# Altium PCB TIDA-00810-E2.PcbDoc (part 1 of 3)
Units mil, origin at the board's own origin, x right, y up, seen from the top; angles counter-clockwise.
Board outline 4527.56 x 3740.16 mil, 4 copper layers (Top Layer, Signal Layer 1, Signal Layer 2, Bottom Layer), stack 25.634 mil thick; 448 components, 198 nets, 1031 pads, 344 vias.
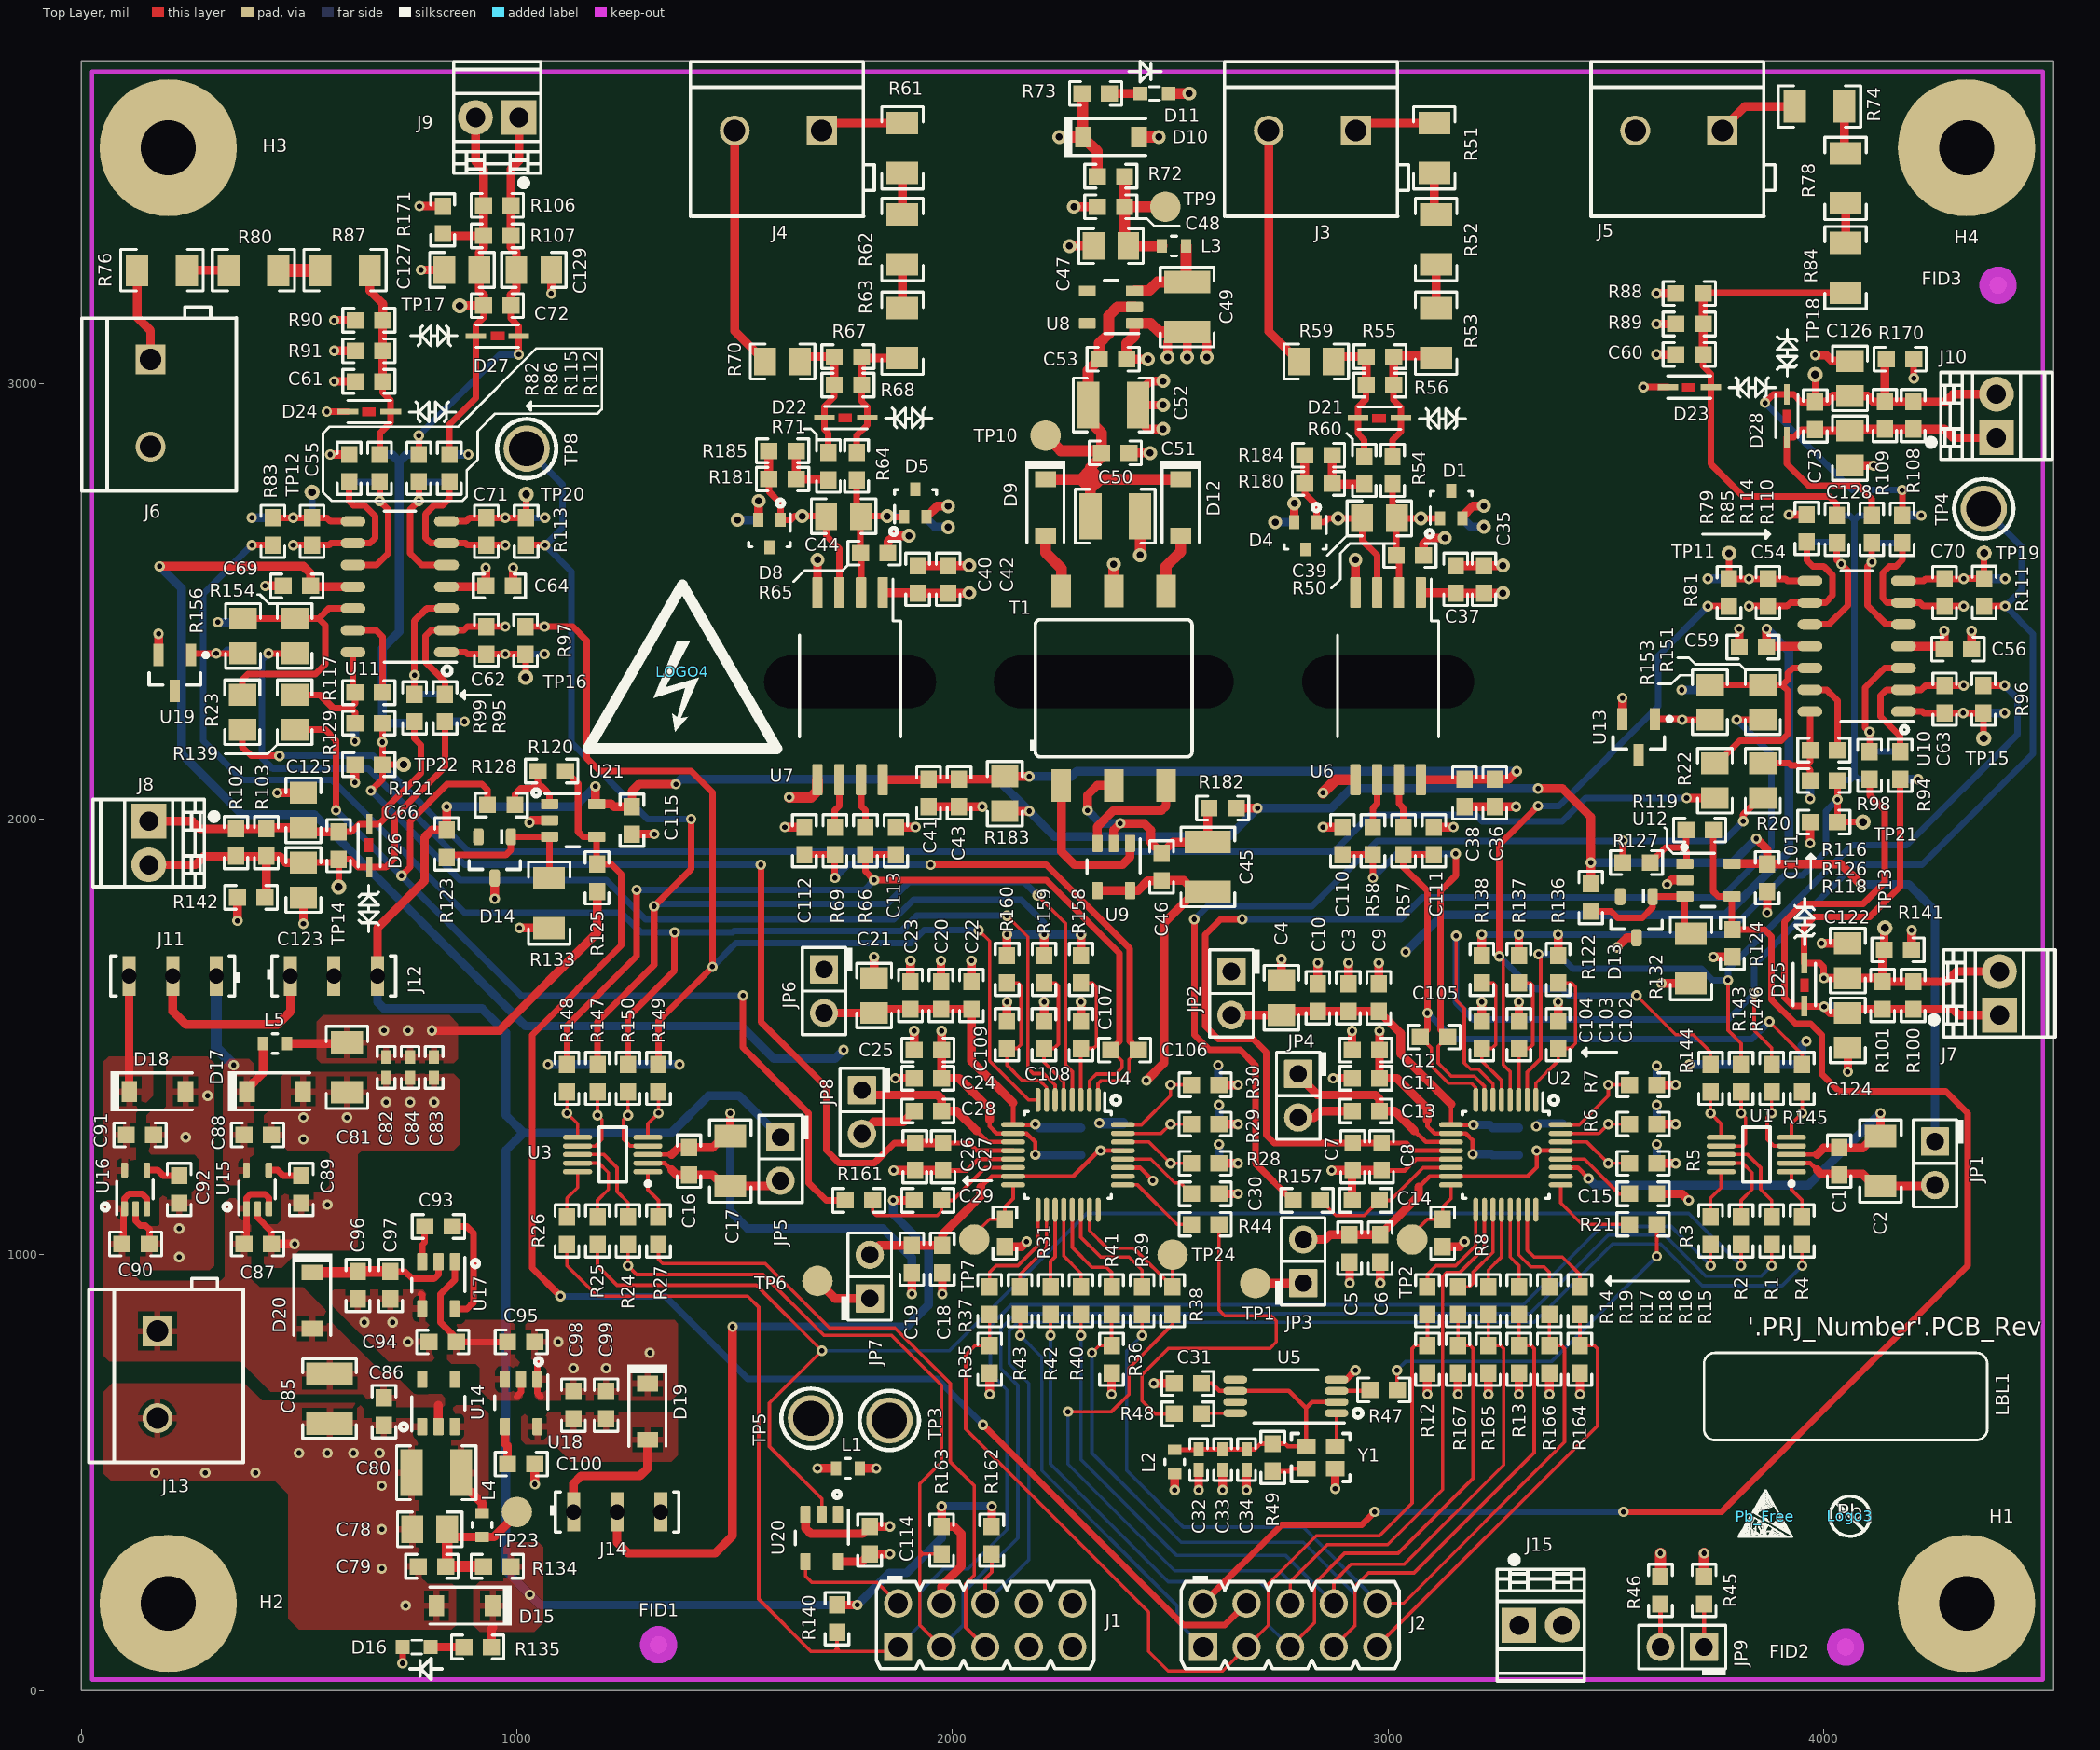
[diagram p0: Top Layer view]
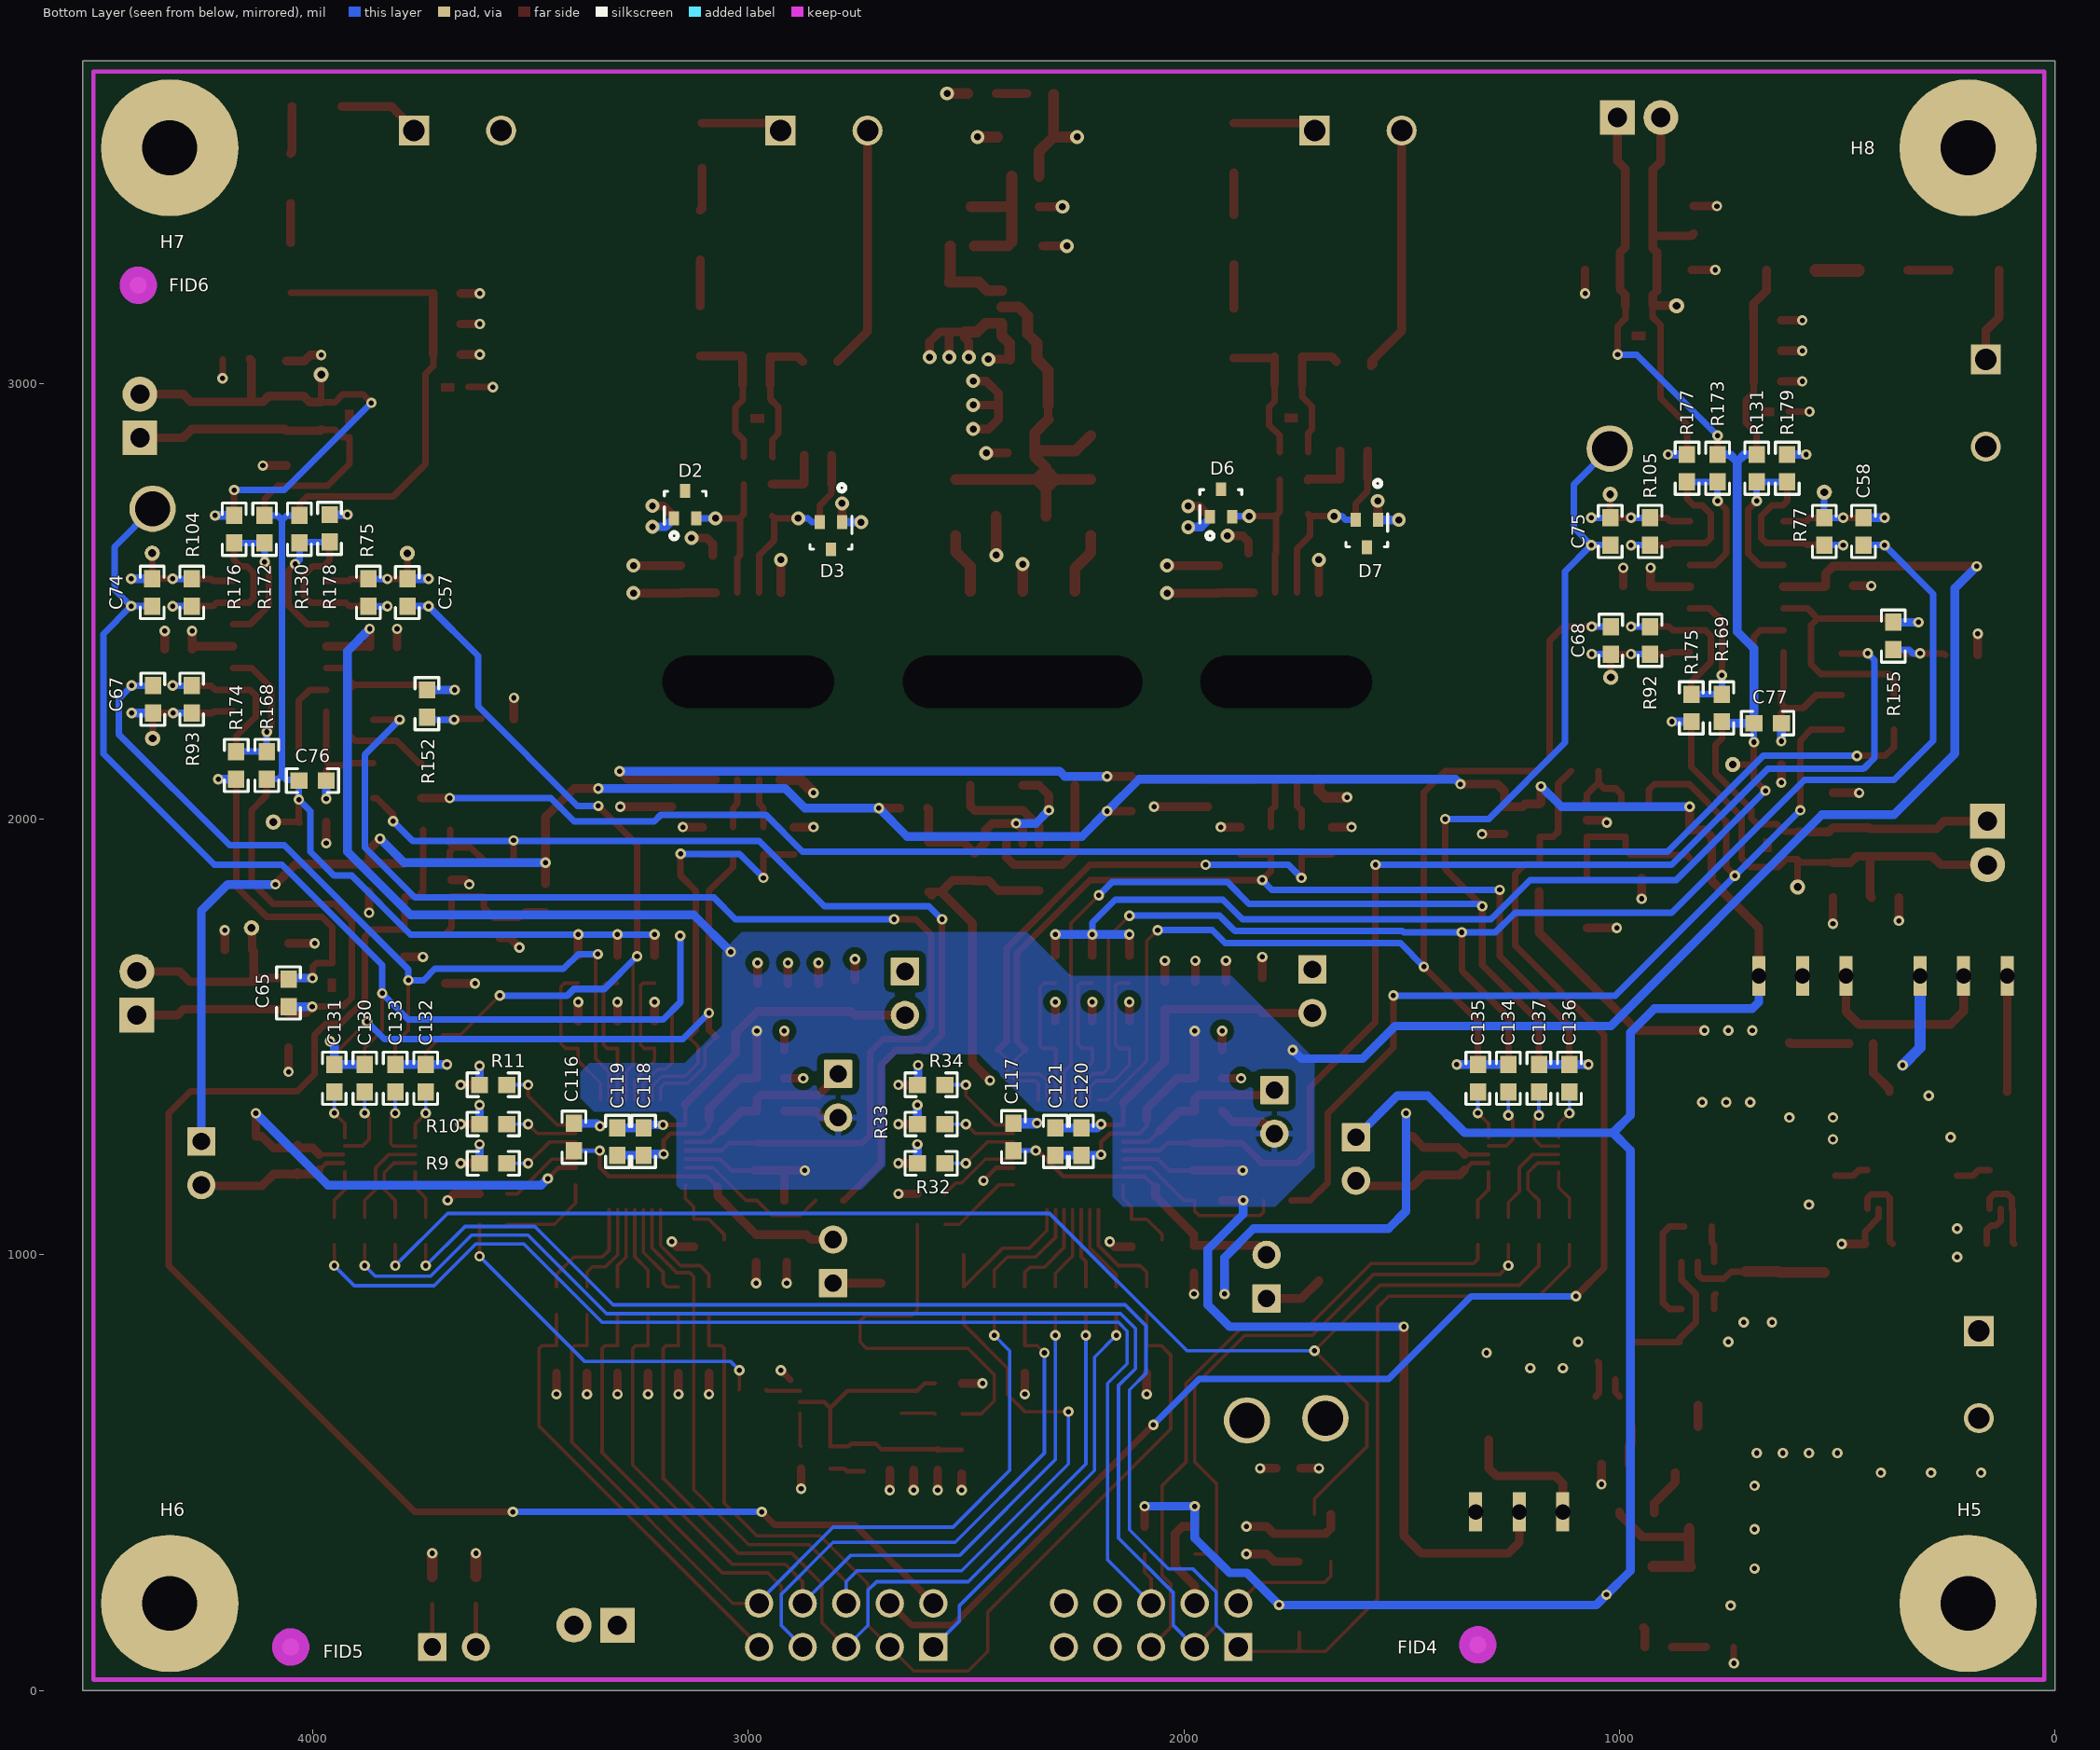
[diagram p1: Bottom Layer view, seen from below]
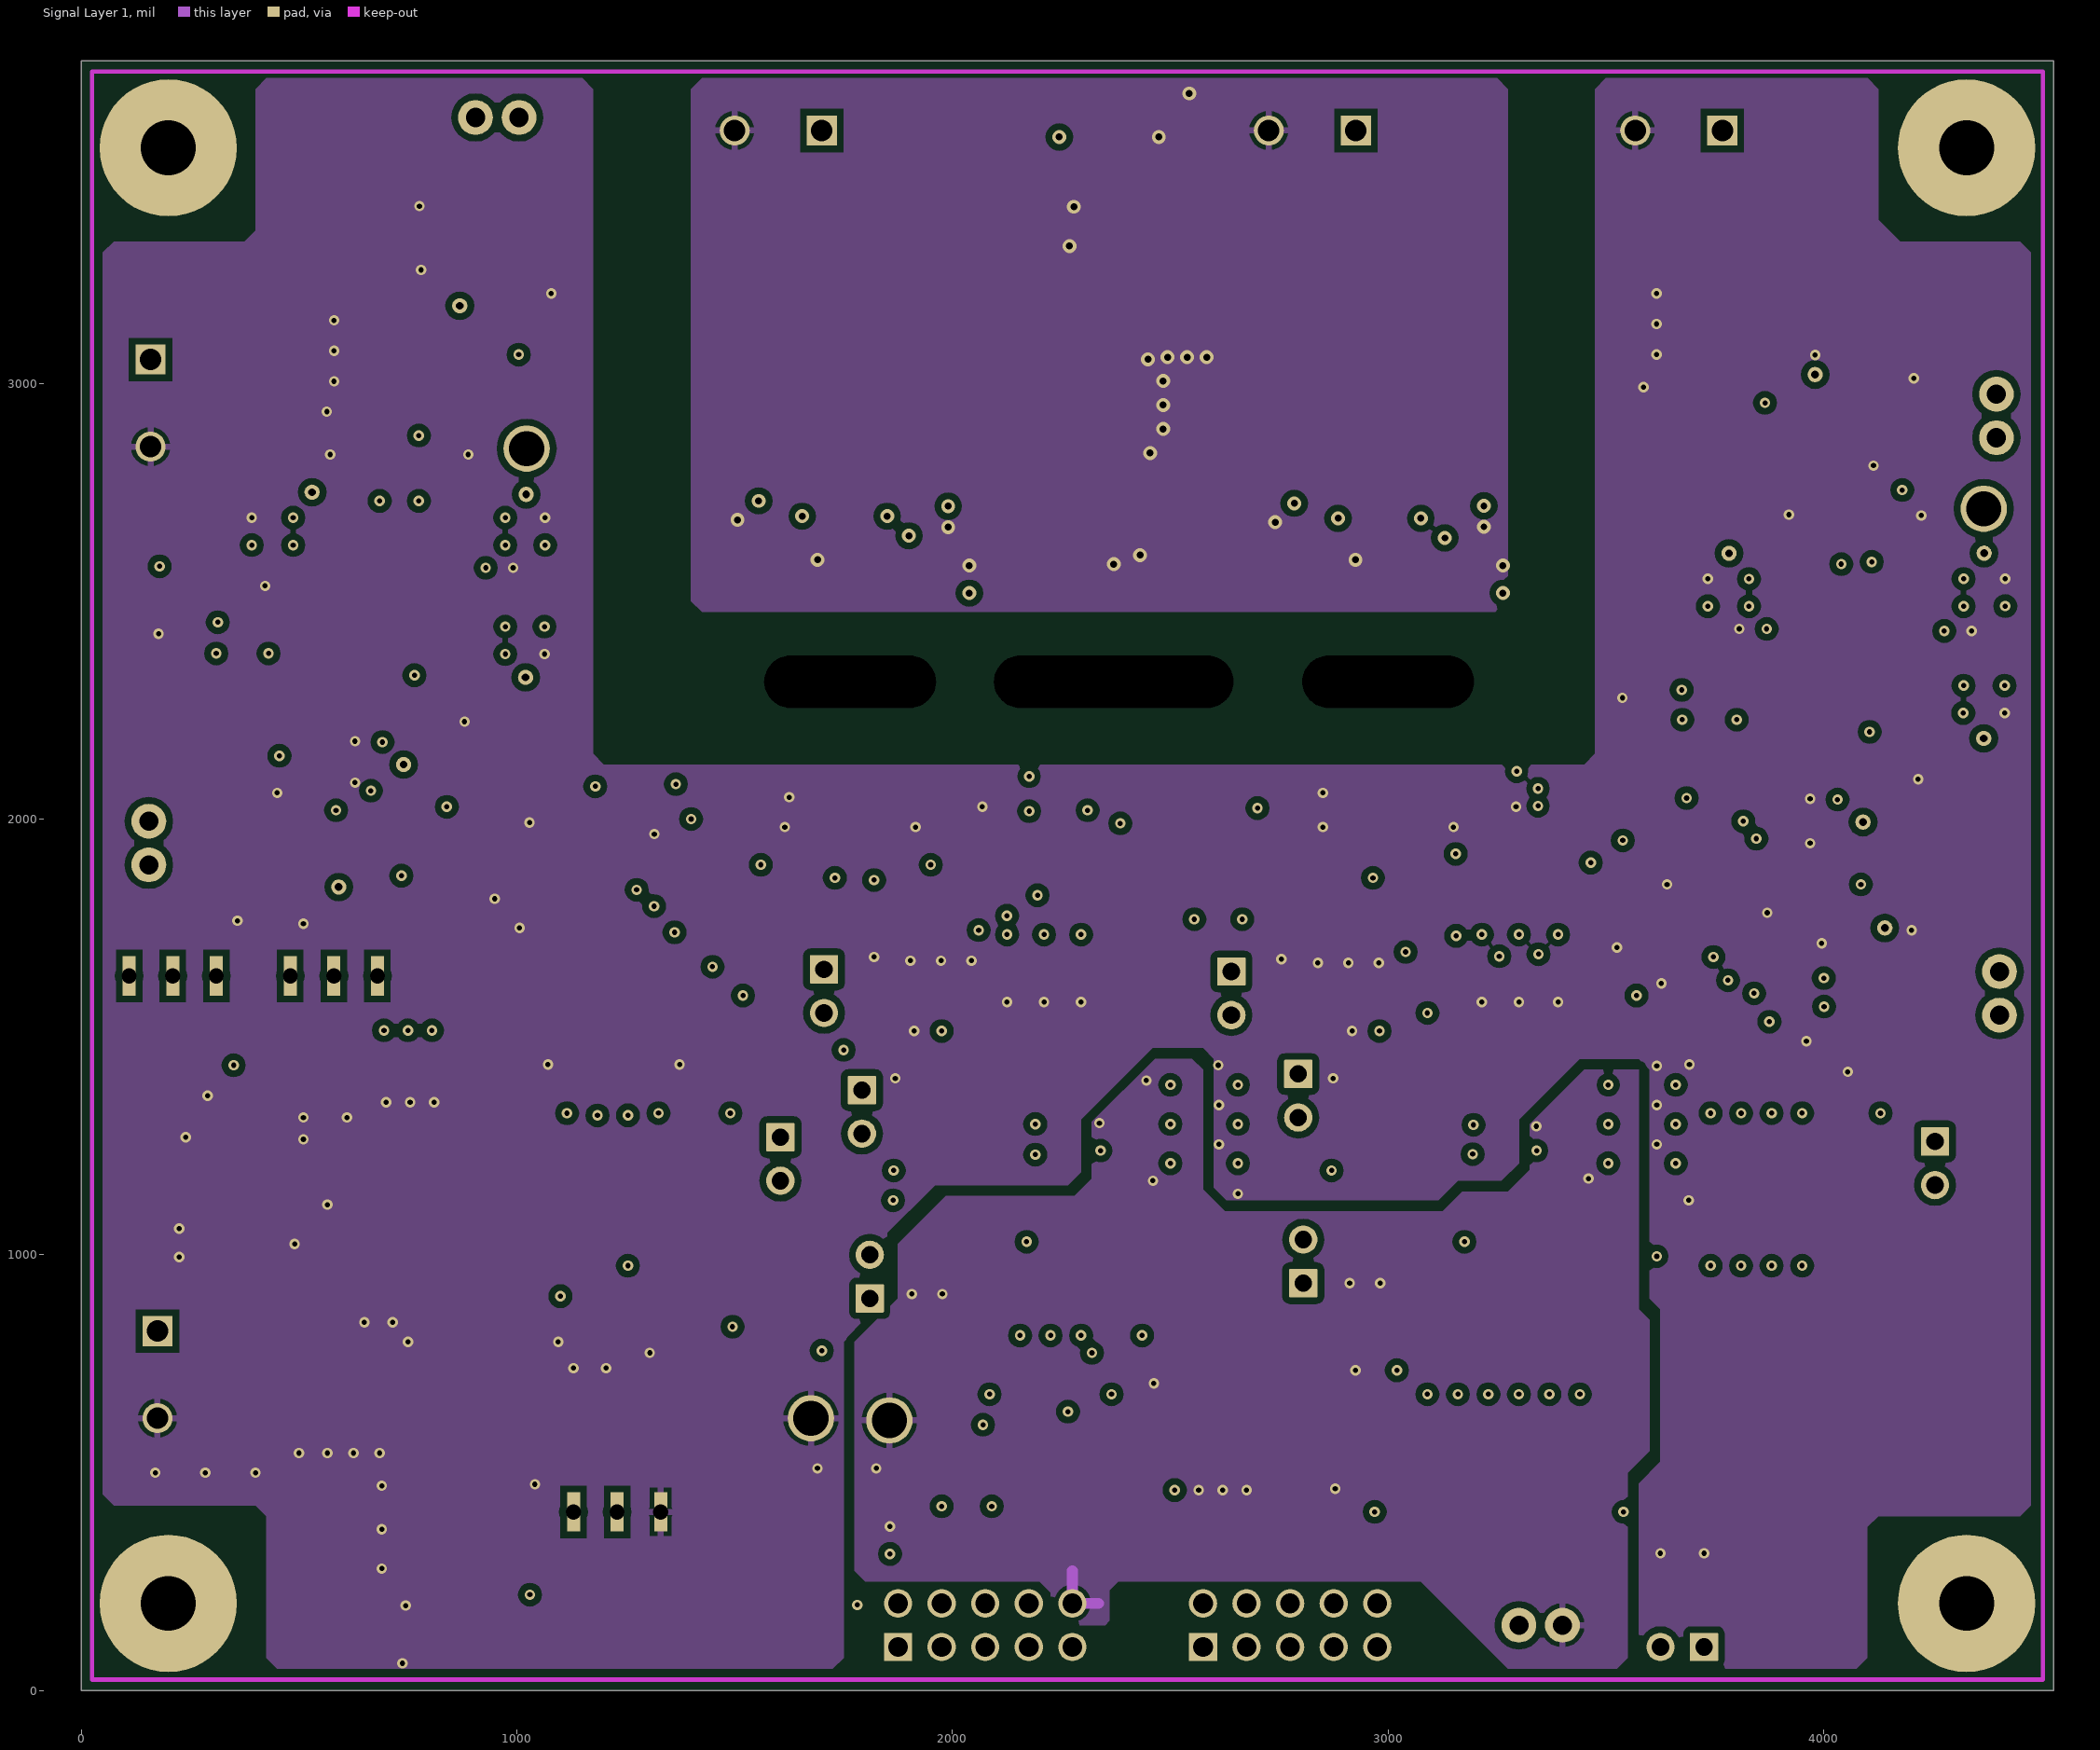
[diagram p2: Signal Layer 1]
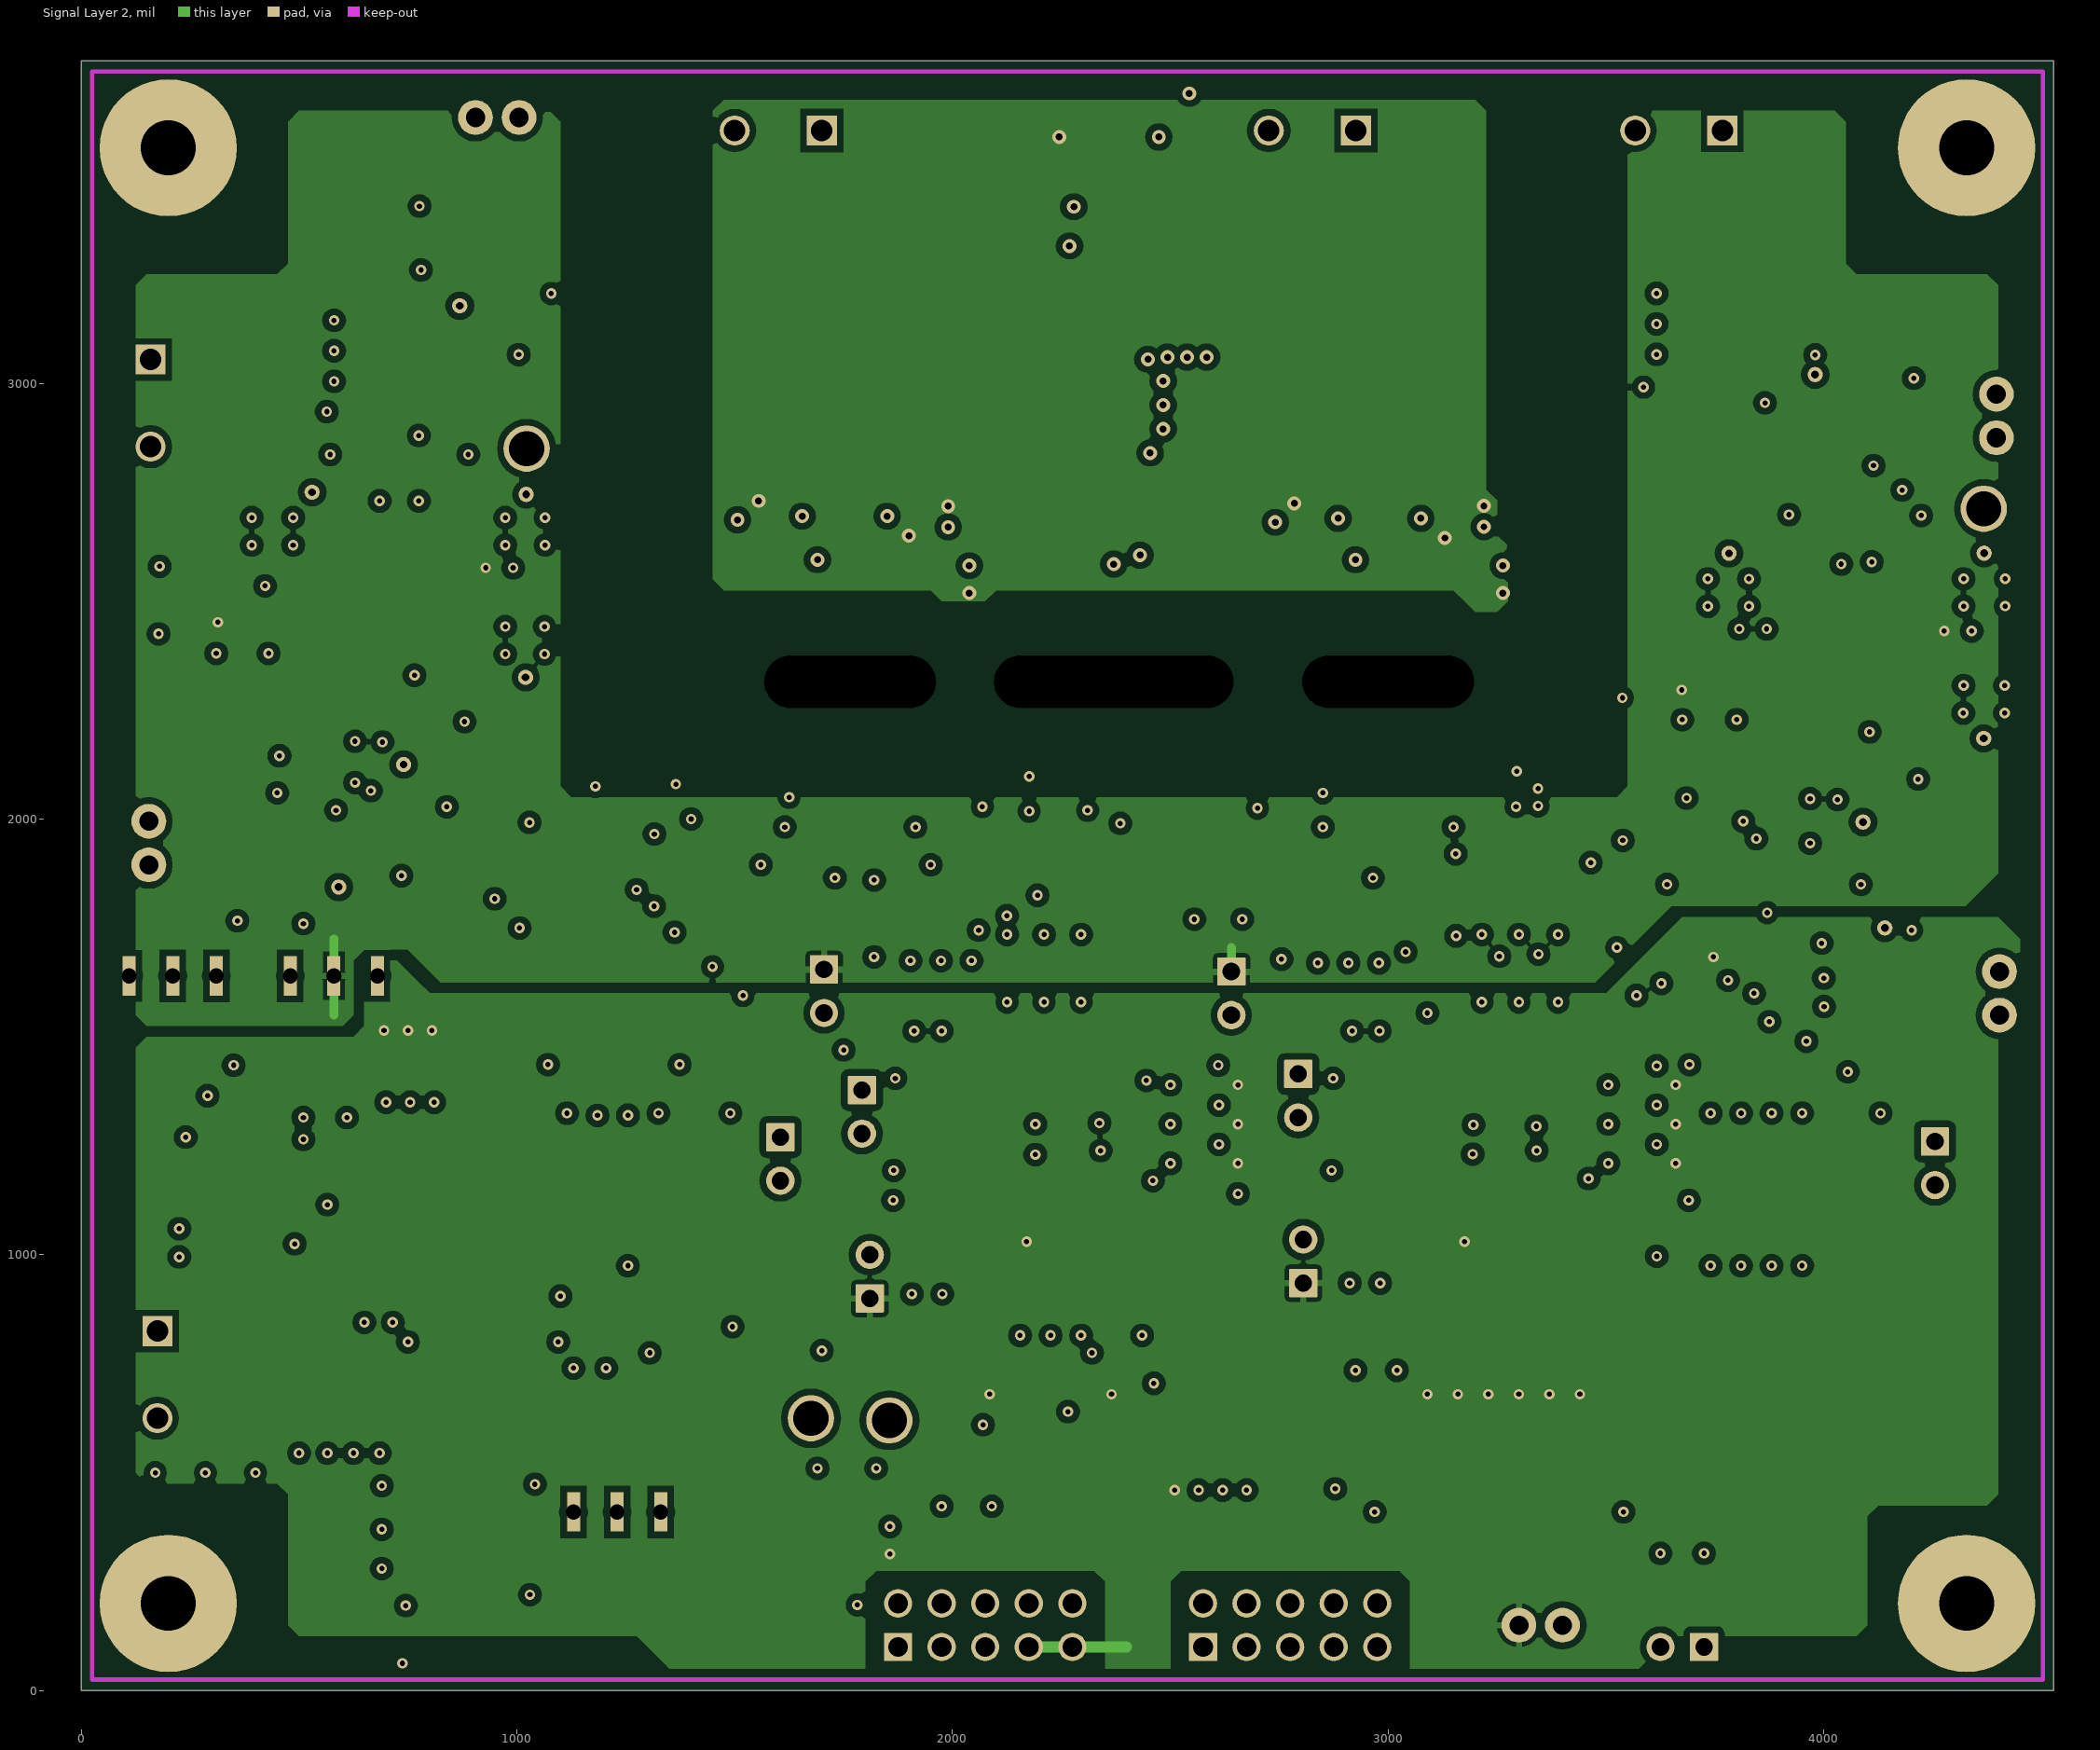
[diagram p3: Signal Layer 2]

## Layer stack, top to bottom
Top Solder: solder mask 0.4, Solder Resist, Dk 3.5
Top Layer: signal copper 1.4
Dielectric1: prepreg 5, FR-4, Dk 4.2
Signal Layer 1: signal copper 1.417
Dielectric 2: core 10, Dk 4.2
Signal Layer 2: signal copper 1.417
Dielectric 3: prepreg 5, Dk 4.2
Bottom Layer: signal copper 1.4
Bottom Solder: solder mask 0.4, Solder Resist, Dk 3.5

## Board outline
0,0 0,3740.16 4527.56,3740.16 4527.56,0

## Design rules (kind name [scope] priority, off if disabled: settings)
AcuteAngle [All] p1: minimum=4.50000000000000E+0001 checktracksonly=FALSE
AssemblyTestPointUsage [All] p1: valid=2
Clearance Clearance_hole [InPadClass('holes') vs InPolygon] p1: gap=40
Clearance Clearance_via [IsVia vs IsPad] p2: gap=7.87
Clearance Clearance_BoardEdge_MountingHoles [OnCopper and InComponentClass('Mounting Holes') vs IsKeepOut] p3: gap=10
Clearance Clearance_BoardEdge_Poly [OnCopper and InPoly vs IsKeepOut] p4: gap=10
Clearance Clearance_poly_poly [InPoly vs InPoly] p5: gap=20
Clearance Clearance_Poly [InPolygon] p6: gap=15
Clearance [All] p7: gap=7.87 except(8: Track-Track)
ComponentClearance ComponentClearance_Shunt [InComponentClass('Header') vs InComponentClass('Shunt')] p1: gap=0 collisioncheckmode=3 verticalgap=0 showdistances=FALSE
ComponentClearance ComponentClearance_MountingHoles_FiducialMarks [InComponentClass('Mounting Holes') vs InComponentClass('FiducialMark')] p2: gap=50 collisioncheckmode=3 verticalgap=10 showdistances=FALSE
ComponentClearance ComponentClearance_Logo [InComponentClass('Logo')] p3: gap=50 collisioncheckmode=3 verticalgap=10 showdistances=FALSE
ComponentClearance ComponentClearance_ScrewToNut [(HasFootprint('NY PMS 440 0025 PH')) vs (HasFootprint('Keystone_1902C'))] p4: gap=5 collisioncheckmode=3 verticalgap=10 showdistances=FALSE
ComponentClearance ComponentClearance_MountingHoles [InComponentClass('Mounting Holes')] p5: gap=250 collisioncheckmode=3 verticalgap=100000 showdistances=FALSE
ComponentClearance ComponentClearance_SmallPassives [HasFootprint('0201*') or HasFootprint('0402*') or HasFootprint('0508') or HasFootprint('0603*') or HasFootprint('0612') or HasFootprint('0805*') or HasFootprint('0815*') or HasFootprint('0830*') or HasFootprint('1206*') or HasFootprint('1210*') or HasFootprint('1808*') or HasFootprint('1812*') or HasFootprint('1825*') or HasFootprint('2010*') or HasFootprint('2220*') or HasFootprint('2225*') or HasFootprint('2512*') or HasFootprint('2728*') or HasFootprint('3518*') vs HasFootprint('0201*') or HasFootprint('0402*') or HasFootprint('0508') or HasFootprint('0603*') or HasFootprint('0612') or HasFootprint('0805*') or HasFootprint('0815*') or HasFootprint('0830*') or HasFootprint('1206*') or HasFootprint('1210*') or HasFootprint('1808*') or HasFootprint('1812*') or HasFootprint('1825*') or HasFootprint('2010*') or HasFootprint('2220*') or HasFootprint('2225*') or HasFootprint('2512*') or HasFootprint('2728*') or HasFootprint('3518*')] p6: gap=20 collisioncheckmode=3 verticalgap=10 showdistances=FALSE
ComponentClearance ComponentClearance_THtoSMT [IsThruComponent vs IsSMTComponent] p7: gap=100 collisioncheckmode=3 verticalgap=30 showdistances=FALSE
ComponentClearance ComponentClearance_THtoTH [IsThruComponent vs IsThruComponent] p8: gap=118.11 collisioncheckmode=3 verticalgap=30 showdistances=FALSE
ComponentClearance [All] p9: gap=40 collisioncheckmode=3 verticalgap=10 showdistances=FALSE
DiffPairsRouting [All] p1: maxlimit=100 minlimit=10 mostfreqgap=10 toplayer_minwidth=15 toplayer_maxwidth=15 toplayer_prefwidth=15 midlayer1_minwidth=15 midlayer1_maxwidth=15 midlayer1_prefwidth=15 midlayer2_minwidth=15 midlayer2_maxwidth=15 midlayer2_prefwidth=15 bottomlayer_minwidth=15 bottomlayer_maxwidth=15 bottomlayer_prefwidth=15 maxuncoupledlength=1000
FabricationTestPointUsage TestPointUsage [All] p1: valid=2 allowmultiple=FALSE
FabricationTestpoint Testpoint [All] p1: side=3 testpointundercomponent=TRUE minsize=40 maxsize=100 preferedsize=60 minholesize=0 maxholesize=40 preferedholesize=32 testpointgrid=1 allowsidetop=TRUE allowsidebottom=TRUE usegrid=TRUE gridtolerance=0.01
FanoutControl Fanout_LCC [IsLCC] p1: bgadir=Out bgaviamode=Centered fanoutstyle=Auto fanoutdirection=Alternating viagrid=1 // Fanout_LCC (Default Rule)
FanoutControl Fanout_BGA [IsBGA] p2: bgadir=Out bgaviamode=Centered fanoutstyle=Auto fanoutdirection=Alternating viagrid=1 // Fanout_BGA (Default Rule)
FanoutControl Fanout_Default [All] p4: bgadir=Out bgaviamode=Centered fanoutstyle=Auto fanoutdirection=Alternating viagrid=1 // Fanout_Default (Default Rule)
FanoutControl Fanout_Small [(CompPinCount < 5)] p5: bgadir=Out bgaviamode=Centered fanoutstyle=Auto fanoutdirection=OutThenIn viagrid=1 // Fanout_Small (Default Rule)
HoleSize [All] p1: absolutevalues=TRUE maxlimit=550 minlimit=7.87 maxpercent=80.000 minpercent=20.000
MinimumAnnularRing MinimumAnnularRing_ThermalPadVias [IsVia and InAnyComponent] p1: minimumring=5.9
MinimumAnnularRing [All] p2: minimumring=5.9
MinimumSolderMaskSliver MinimumSolderMaskSliver_Logo [InComponentClass('Logo') vs InComponentClass('Logo')] p1: minsoldermaskwidth=0.7
MinimumSolderMaskSliver [All] p2: minsoldermaskwidth=3.94
PlaneConnect [All] p1: planeconnectstyle=Direct reliefexpansion=10 reliefentries=4 reliefconductorwidth=10 reliefairgap=10
PolygonConnect PolygonConnect_Via [All vs IsVia] p1: connectstyle=Direct reliefconductorwidth=10 reliefentries=4 polygonreliefangle="90 Angle" airgapwidth=10
PolygonConnect [All] p2: connectstyle=Relief reliefconductorwidth=15 reliefentries=4 polygonreliefangle="90 Angle" airgapwidth=10
RoutingVias ThermalPadVias [IsVia and InAnyComponent] p1: holewidth=7.87 width=19.68 viastyle="Through Hole" minholewidth=7.87 minwidth=19.68 maxholewidth=12.99 maxwidth=23.62
RoutingVias [All] p2: holewidth=12 width=24 viastyle="Through Hole" minholewidth=7.87 minwidth=19.68 maxholewidth=16 maxwidth=32
SMDToCorner [All] p1: distance=30000
SilkToSilkClearance SilkToSilkClearance_Pb-FreeLogo [(HasFootprint('Pb-Free_Overlay_Medium') OR HasFootprint('Pb-Free_Overlay_Small')) vs (HasFootprint('Pb-Free_Overlay_Medium') OR HasFootprint('Pb-Free_Overlay_Small'))] p1: silktosilkclearance=0
SilkToSilkClearance [All] p2: silktosilkclearance=5
SilkToSolderMaskClearance SilkscreenOverComponentPads [IsPad] p1: minsilkscreentomaskgap=5 clearancetoexposedcopper=TRUE
SolderMaskExpansion [All] p1: expansion=1.97
Width [All] p1: maxlimit=100 minlimit=6 preferedwidth=8 checkconnectedcopper=TRUE
16 further rules are at their usual default settings.

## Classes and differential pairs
component class TIDA-00810_Reference: C76 C77 C101 C115 D13 D14 R20 R22 R23 R116 R117 R118 R119 R120 R121 R122 R123 R124 R125 R126 R127 R128 R129 R132 R133 R139 R151 R152 R153 R154 R155 R156 TP21 TP22 U12 U13 U19 U21
component class "TIDA-00810_POWER SUPPLY": C78 C79 C80 C81 C82 C83 C84 C85 C86 C87 C88 C89 C90 C91 C92 C93 C94 C95 C96 C97 C98 C99 C100 D15 D16 D17 D18 D19 D20 FB4 FB5 J11 J12 J13 J14 L4 L5 R134 R135 SH-J9 SH-J10 SH-J11 TP23 U14 U15 U16 U17 U18
component class TIDA-00810_OP-AMP: C54 C55 C56 C57 C58 C59 C60 C61 C62 C63 C64 C65 C66 C67 C68 C69 C70 C71 C72 C73 C74 C75 C122 C123 C124 C125 C126 C127 C128 C129 D23 D24 D25 D26 D27 D28 J5 J6 J7 J8 J9 J10 R74 R75 R76 R77 R78 R79 R80 R81 R82 R83 R84 R85 R86 R87 R88 R89 R90 R91 R92 R93 R94 R95 R96 R97 R98 R99 R100 R101 R102 R103 R104 R105 R106 R107 R108 R109 R110 R111 R112 R113 R114 R115 R130 R131 R141 R142 R168 R169 R170 R171 R172 R173 R174 R175 R176 R177 R178 R179 TP4 TP8 TP11 TP12 TP13 TP14 TP15 TP16 TP17 TP18 TP19 TP20 U10 U11
component class "TIDA-00810_Isolation Amplifier": C35 C36 C37 C38 C39 C40 C41 C42 C43 C44 C45 C46 C47 C48 C49 C50 C51 C52 C53 C110 C111 C112 C113 D1 D2 D3 D4 D5 D6 D7 D8 D9 D10 D11 D12 D21 D22 FB3 J3 J4 L3 R50 R51 R52 R53 R54 R55 R56 R57 R58 R59 R60 R61 R62 R63 R64 R65 R66 R67 R68 R69 R70 R71 R72 R73 R180 R181 R182 R183 R184 R185 T1 TP9 TP10 U6 U7 U8 U9
component class TIDA-00810_Buffer: C31 C32 C33 C34 L2 R47 R48 R49 U5 Y1
component class TIDA-00810_ADC2: C16 C17 C18 C19 C20 C21 C22 C23 C24 C25 C26 C27 C28 C29 C30 C106 C107 C108 C109 C117 C120 C121 C134 C135 C136 C137 JP5 JP6 JP7 JP8 R24 R25 R26 R27 R28 R29 R30 R31 R32 R33 R34 R35 R36 R37 R38 R39 R40 R41 R42 R43 R44 R147 R148 R149 R150 R158 R159 R160 R161 TP6 TP7 TP24 U3 U4
component class TIDA-00810_ADC1: C1 C2 C3 C4 C5 C6 C7 C8 C9 C10 C11 C12 C13 C14 C15 C102 C103 C104 C105 C114 C116 C118 C119 C130 C131 C132 C133 J1 J2 J15 JP1 JP2 JP3 JP4 JP9 L1 R1 R2 R3 R4 R5 R6 R7 R8 R9 R10 R11 R12 R13 R14 R15 R16 R17 R18 R19 R21 R45 R46 R136 R137 R138 R140 R143 R144 R145 R146 R157 R162 R163 R164 R165 R166 R167 TP1 TP2 TP3 TP5 U1 U2 U20
component class Header: J1 J2 J11 J12 J14 JP1 JP2 JP3 JP4 JP5 JP6 JP7 JP8 JP9
component class Label: LBL1
component class AssemblyNote: ZZ1 ZZ2 ZZ3 ZZ4
component class FiducialMark: FID1 FID2 FID3 FID4 FID5 FID6
component class TIDA-00810_EVM_Hardware: FID1 FID2 FID3 FID4 FID5 FID6 H1 H2 H3 H4 H5 H6 H7 H8 LBL1 Logo3 LOGO4 Pb_Free ZZ1 ZZ2 ZZ3 ZZ4
component class "Mounting Holes": H1 H2 H3 H4

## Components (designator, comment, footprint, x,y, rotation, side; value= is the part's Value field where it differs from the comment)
C1 "" 0603#1 4035.13,1215 r90 top
C2 "GMK316AB7106KL" 1206 4130.13,1215 r90 top
C3 "06033C104JAT2A" 0603#1 2908.57,1590 r90 top
C4 "GRM21BR71A106KE51L" 0805_HV 2755.07,1590 r90 top
C5 "06031C103KAT2A" 0603#1 2911.57,1015 r270 top
C6 "GRM188R71E105KA12D" 0603#1 2981.57,1015 r270 top
C7 "GRM188R71E105KA12D" 0603#1 2918.57,1225 r90 top
C8 "06033C104JAT2A" 0603#1 2985.07,1225 r90 top
C9 "06031C103KAT2A" 0603#1 2978.57,1590 r90 top
C10 "GRM188R71E105KA12D" 0603#1 2838.57,1590 r90 top
C11 "06031C103KAT2A" 0603#1 2948.57,1405 r180 top
C12 "GRM188R71E105KA12D" 0603#1 2948.57,1470 r180 top
C13 "C0603C274K4RACTU" 0603#1 2948.57,1330 r180 top
C14 "GRM188R71E105KA12D" 0603#1 2948.57,1125 r180 top
C15 "GRM188R71E105KA12D" 0603#1 3585.07,1140 r0 top
C16 "" 0603#1 1395.07,1215 r90 top (schematic designator C1)
C17 "GMK316AB7106KL" 1206 1490.07,1215 r90 top (schematic designator C2)
C18 "06031C103KAT2A" 0603#1 1976.57,990 r270 top (schematic designator C6)
C19 "GRM188R71E105KA12D" 0603#1 1906.57,990 r270 top (schematic designator C5)
C20 "06033C104JAT2A" 0603#1 1973.57,1595 r90 top (schematic designator C3)
C21 "GRM21BR71A106KE51L" 0805_HV 1820.07,1595 r90 top (schematic designator C4)
C22 "06031C103KAT2A" 0603#1 2043.57,1595 r90 top (schematic designator C9)
C23 "GRM188R71E105KA12D" 0603#1 1903.57,1595 r90 top (schematic designator C10)
C24 "06031C103KAT2A" 0603#1 1943.57,1405 r180 top (schematic designator C11)
C25 "GRM188R71E105KA12D" 0603#1 1943.57,1470 r180 top (schematic designator C12)
C26 "GRM188R71E105KA12D" 0603#1 1913.57,1225 r90 top (schematic designator C7)
C27 "06033C104JAT2A" 0603#1 1978.57,1225 r90 top (schematic designator C8)
C28 "C0603C274K4RACTU" 0603#1 1943.57,1330 r180 top (schematic designator C13)
C29 "GRM188R71E105KA12D" 0603#1 1943.57,1125 r180 top (schematic designator C14)
C30 "GRM188R71E105KA12D" 0603#1 2580.07,1140 r0 top (schematic designator C15)
C31 "C0603C104K4RACTU" 0603#1 2540,705 r180 top
C32 "GCM155R71H103KA55D" 0402 2565,530 r270 top
C33 "GRM155R61E102KA01D" 0402 2620,530 r270 top
C34 "CC0402KRX7R9BB101" 0402 2675,530 r270 top
C35 "" 0603#1 3220,2550 r90 top
C36 "" 0603#1 3245,2060 r90 top
C37 "GRM188R71C105KA12D" 0603#1 3155,2550 r270 top
C38 "GRM188R71C105KA12D" 0603#1 3175,2060 r270 top
C39 "08055A331KAT2A" 0805_HV 2980,2690 r180 top
C40 "" 0603#1 1920,2550 r90 top
C41 "" 0603#1 1945,2060 r90 top
C42 "GRM188R71C105KA12D" 0603#1 1990,2550 r270 top
C43 "GRM188R71C105KA12D" 0603#1 2015,2060 r270 top
C44 "08055A331KAT2A" 0805_HV 1750,2695 r180 top
C45 "" 1210 2586,1890 r90 top
C46 "" 0603#1 2480,1890 r90 top
C47 "" 0805_HV 2363.5,3315 r0 top
C48 "" 0603#1 2363.5,3405 r180 top
C49 "" 1210 2538.5,3175 r90 top
C50 "" 1210 2373.5,2695 r0 top
C51 "" 0603#1 2373.5,2840 r0 top
C52 "" 1210 2368.5,2950 r180 top
C53 "" 0603#1 2368.5,3055 r0 top
C54 "06033C101KAT2A" 0603#1 3871.73,2519.78 r90 top
C55 "06033C101KAT2A" 0603#1 530,2660 r90 top
C56 "06033C104JAT2A" 0603#1 4307.87,2390 r180 top
C57 "06033C101KAT2A" 0603#1 3782.3,2519.78 r90 bottom
C58 "06033C101KAT2A" 0603#1 440,2660 r90 bottom
C59 "06033C104JAT2A" 0603#1 3837.3,2394.78 r0 top
C60 "C1608C0G1H102J" 0603#1 3691.18,3066.07 r0 top
C61 "C1608C0G1H102J" 0603#1 660.37,3004.39 r0 top
C62 "06033C101KAT2A" 0603#1 930,2410 r270 top
C63 "06033C101KAT2A" 0603#1 4277.3,2274.78 r270 top
C64 "06033C104JAT2A" 0603#1 960,2535 r180 top
C65 "06033C101KAT2A" 0603#1 4055,1601 r270 bottom
C66 "06033C101KAT2A" 0603#1 591.07,1939.04 r90 top
C67 "06033C101KAT2A" 0603#1 4366.41,2274.78 r270 bottom
C68 "06033C101KAT2A" 0603#1 1020,2410 r270 bottom
C69 "06033C104JAT2A" 0603#1 495,2535 r0 top
C70 "06033C101KAT2A" 0603#1 4277.3,2519.78 r90 top
C71 "06033C101KAT2A" 0603#1 930,2660 r90 top
C72 "06033C101KAT2A" 0603#1 955,3178.19 r0 top
C73 "06033C101KAT2A" 0603#1 3980,2925 r270 top
C74 "06033C101KAT2A" 0603#1 4367.87,2520 r90 bottom
C75 "06033C101KAT2A" 0603#1 1021.32,2660 r90 bottom
C76 "06033C104JAT2A" 0603#1 4000,2088.07 r0 bottom
C77 "06033C104JAT2A" 0603#1 660,2220 r0 bottom
C78 "" 0805_HV 800,370 r0 top
C79 "" 0603#1 805,285 r180 top
C80 "" 1210 815,500 r0 top
C81 "GMK316AB7106KL" 1206 610,1430 r270 top
C82 "GCM155R71H103KA55D" 0402 700,1430 r270 top
C83 "GRM155R61E102KA01D" 0402 810,1430 r270 top
C84 "CC0402KRX7R9BB101" 0402 755,1430 r270 top
C85 "" 1210 570,670 r90 top
C86 "" 0603#1 695,640 r270 top
C87 "GRM188R71E105KA12D" 0603#1 405,1025 r0 top
C88 "GRM188R71E105KA12D" 0603#1 405,1275 r0 top
C89 "06031C102JAT2A" 0603#1 505,1150 r270 top
C90 "GRM188R71E105KA12D" 0603#1 125,1025 r0 top
C91 "GRM188R71E105KA12D" 0603#1 135,1275 r0 top
C92 "06031C102JAT2A" 0603#1 225,1150 r270 top
C93 "GRM188R71E105KA12D" 0603#1 820,1065 r180 top
C94 "GRM188R71E105KA12D" 0603#1 830,800 r180 top
C95 "06031C103KAT2A" 0603#1 1010,800 r0 top
C96 "GRM188R71E105KA12D" 0603#1 635,930 r270 top
C97 "06031C103KAT2A" 0603#1 710,930 r270 top
C98 "GRM188R71E105KA12D" 0603#1 1130,655 r90 top
C99 "06031C103KAT2A" 0603#1 1205,655 r90 top
C100 "06031C102JAT2A" 0603#1 1010,520 r0 top
C101 "06033C104JAT2A" 0603#1 3870,1865 r90 top
C102 "06033C101KAT2A" 0603#1 3390.07,1505 r90 top
C103 "06033C101KAT2A" 0603#1 3300.07,1505 r90 top
C104 "06033C101KAT2A" 0603#1 3215.07,1505 r90 top
C105 "06031C102JAT2A" 0603#1 3105.07,1500 r180 top
C106 "06031C102JAT2A" 0603#1 2395.07,1470 r180 top (schematic designator C105)
C107 "06033C101KAT2A" 0603#1 2295.07,1505 r90 top (schematic designator C102)
C108 "06033C101KAT2A" 0603#1 2210.07,1505 r90 top (schematic designator C103)
C109 "06033C101KAT2A" 0603#1 2125.07,1505 r90 top (schematic designator C104)
C110 "06033C101KAT2A" 0603#1 2895,1950 r90 top
C111 "06033C101KAT2A" 0603#1 3105,1950 r90 top
C112 "06033C101KAT2A" 0603#1 1660,1950 r90 top
C113 "06033C101KAT2A" 0603#1 1870,1950 r90 top
C114 "06033C104JAT2A" 0603#1 1810,345 r90 top
C115 "06033C104JAT2A" 0603#1 1264.13,1997.05 r90 top
C116 "06031C103KAT2A" 0603#1 3400,1270 r90 bottom
C117 "06031C103KAT2A" 0603#1 2391.05,1270.68 r90 bottom
C118 "GRM188R61E105KA12D" 0603#1 3240,1260 r270 bottom
C119 "GRM188R71H104KA93D" 0603#1 3300,1260 r270 bottom
C120 "GRM188R61E105KA12D" 0603#1 2235,1260 r270 bottom
C121 "GRM188R71H104KA93D" 0603#1 2295,1260 r270 bottom
C122 "CC0805JRNP09BN470" 0805_HV 4055,1675 r90 top
C123 "CC0805JRNP09BN470" 0805_HV 510,1860 r270 top
C124 "CC0805JRNP09BN470" 0805_HV 4055,1515 r90 top
C125 "CC0805JRNP09BN470" 0805_HV 510,2020 r270 top
C126 "CC0805JRNP09BN470" 0805_HV 4060,3011 r90 top
C127 "CC0805JRNP09BN470" 0805_HV 874,3260 r180 top
C128 "CC0805JRNP09BN470" 0805_HV 4060,2851 r90 top
C129 "CC0805JRNP09BN470" 0805_HV 1039,3260 r180 top
C130 "06031C103KAT2A" 0603#1 3880,1405 r90 bottom
C131 "06031C103KAT2A" 0603#1 3950,1405 r90 bottom
C132 "06031C103KAT2A" 0603#1 3740,1405 r90 bottom
C133 "06031C103KAT2A" 0603#1 3810,1405 r90 bottom
C134 "06031C103KAT2A" 0603#1 1255,1405 r90 bottom
C135 "06031C103KAT2A" 0603#1 1325,1405 r90 bottom
C136 "06031C103KAT2A" 0603#1 1115,1405 r90 bottom
C137 "06031C103KAT2A" 0603#1 1185,1405 r90 bottom
D1 "" SOT-323 3144.68,2721.57 r90 top
D2 "" SOT-323 3144.68,2721.57 r90 bottom
D3 "" SOT-323 2810,2650 r270 bottom
D4 "" SOT-323 2810,2650 r270 top
D5 "" SOT-323 1915,2725 r90 top
D6 "" SOT-323 1915,2725 r90 bottom
D7 "" SOT-323 1580,2655 r270 bottom
D8 "" SOT-323 1580,2655 r270 top
D9 "B0520LW-7-F" SOD-123 2213.5,2715 r270 top
D10 "MMSZ5232B-7-F" SOD-123 2363.5,3565 r0 top
D11 "" LED0603AA 2463.5,3665 r180 top
D12 "B0520LW-7-F" SOD-123 2523.5,2715 r270 top
D13 "BAS21-7-F" SOT-23 3570,1775 r270 top
D14 "BAS21-7-F" SOT-23 949.13,1912.05 r270 top
D15 "MMSZ5232B-7-F" SOD-123 880,195 r180 top
D16 "" LED0603AA 770,100 r0 top
D17 "MMSZ4685T1G" SOD-123 445,1375 r0 top
D18 "MMSZ4683T1G" SOD-123 175,1375 r0 top
D19 "MMSZ4683T1G" SOD-123 1300,640 r270 top
D20 "MBR0520LT1G" SOD-123 530,895 r270 top
D21 "PESD3V3L1BA" DIO_SOD323 2980,2920 r180 top
D22 "PESD3V3L1BA" DIO_SOD323 1755,2921.02 r180 top
D23 "PESD3V3L1BA" DIO_SOD323 3691.18,2991.07 r180 top
D24 "PESD3V3L1BA" DIO_SOD323 661.35,2934.86 r180 top
D25 "PESD3V3L1BA" DIO_SOD323 3955,1620 r270 top
D26 "PESD3V3L1BA" DIO_SOD323 661.07,1939.04 r90 top
D27 "PESD3V3L1BA" DIO_SOD323 955,3108.19 r0 top
D28 "PESD3V3L1BA" DIO_SOD323 3915,2925 r270 top
FID1 "Fiducial" Fiducial10-20 1325.32,105 r90 top
FID2 "Fiducial" Fiducial10-20 4050,100 r90 top
FID3 "Fiducial" Fiducial10-20 4400,3225 r90 top
FID4 "Fiducial" Fiducial10-20 1325.32,105 r180 bottom
FID5 "Fiducial" Fiducial10-20 4050,100 r180 bottom
FID6 "Fiducial" Fiducial10-20 4400,3225 r180 bottom
H1 "NY PMS 440 0025 PH" "NY PMS 440 0025 PH" 4327.56,200 r0 top
H2 "NY PMS 440 0025 PH" "NY PMS 440 0025 PH" 200,200 r0 top
H3 "NY PMS 440 0025 PH" "NY PMS 440 0025 PH" 200,3540.16 r0 top
H4 "NY PMS 440 0025 PH" "NY PMS 440 0025 PH" 4327.56,3540.16 r0 top
H5 "1902C" Keystone_1902C 199.77,200.01 r180 bottom
H6 "1902C" Keystone_1902C 4327.56,200 r180 bottom
H7 "1902C" Keystone_1902C 4327.33,3540.17 r180 bottom
H8 "1902C" Keystone_1902C 200,3540.16 r180 bottom
J1 "61301021121" WURTH_61301021121 2075,150 r0 top
J2 "61301021121" WURTH_61301021121 2775,150 r0 top
J3 "ED120/2DS" CONN_ED120-2DS 2825.96,3580 r90 top
J4 "ED120/2DS" CONN_ED120-2DS 1600,3580 r90 top
J5 "ED120/2DS" CONN_ED120-2DS 3667.01,3580 r90 top
J6 "ED120/2DS" CONN_ED120-2DS 159.17,2954.39 r180 top
J7 "CON-OSTVN02A150" CN2_MTB_P100_PD80_D1.1_S5.54X6.5_STACK 4403,1600 r90 top
J8 "CON-OSTVN02A150" CN2_MTB_P100_PD80_D1.1_S5.54X6.5_STACK 155,1945 r270 top
J9 "CON-OSTVN02A150" CN2_MTB_P100_PD80_D1.1_S5.54X6.5_STACK 955,3609.88 r180 top
J10 "CON-OSTVN02A150" CN2_MTB_P100_PD80_D1.1_S5.54X6.5_STACK 4396.3,2924.99 r90 top
J11 "5-146280-3" TE_5-146280-3 210,1640 r180 top
J12 "5-146280-3" TE_5-146280-3 580,1640 r0 top
J13 "ED120/2DS" CONN_ED120-2DS 175,725 r180 top
J14 "5-146280-3" TE_5-146280-3 1230,410 r0 top
J15 "CON-OSTVN02A150" CN2_MTB_P100_PD80_D1.1_S5.54X6.5_STACK 3350,150 r0 top
JP1 "5-146280-2" TSW-102-07-G-S 4255.13,1210 r270 top
JP2 "5-146280-2" TSW-102-07-G-S 2640.07,1600 r270 top
JP3 "5-146280-2" TSW-102-07-G-S 2805.07,985 r90 top
JP4 "5-146280-2" TSW-102-07-G-S 2793.58,1365 r270 top
JP5 "5-146280-2" TSW-102-07-G-S 1605,1220 r270 top (schematic designator JP1)
JP6 "5-146280-2" TSW-102-07-G-S 1705.07,1605 r270 top (schematic designator JP2)
JP7 "5-146280-2" TSW-102-07-G-S 1810,950 r90 top (schematic designator JP3)
JP8 "5-146280-2" TSW-102-07-G-S 1792,1328 r270 top (schematic designator JP4)
JP9 "5-146280-2" TSW-102-07-G-S 3675,100 r180 top
L1 "MMZ1608B102CTA00" MMZ1608_095 1760,510 r0 top
L2 "MMZ1608B102CTA00" MMZ1608_095 2510,525 r90 top
L3 "MMZ1608B102CTA00" MMZ1608_095 2508.5,3315 r180 top
L4 "MMZ1608B102CTA00" MMZ1608_095 920,380 r270 top
L5 "MMZ1608B102CTA00" MMZ1608_095 445,1485 r0 top
LBL1 "Size: 0.65\" x 0.20 \"" Label_650x200 4050,675 r0 top
Logo3 "Pb-Free Symbol" Pb-Free_Overlay_Small 4060,400 r0 top
LOGO4 "DANGER HIGH VOLTAGE" IEC_HighVoltage_medium 1380,2337 r0 top
Pb_Free "ESD Susceptible" ESD_Overlay_small 3865,400 r0 top
R1 "RC0603JR-070RL" 0603#1 3880.07,1055 r270 top
R2 "RC0603JR-070RL" 0603#1 3810.13,1055 r90 top
R3 "RC0603JR-070RL" 0603#1 3740.07,1055 r270 top
R4 "RC0603JR-070RL" 0603#1 3950.07,1055 r270 top
R5 "RC0603FR-07510RL" 0603#1 3585.07,1210 r0 top
R6 "RC0603FR-07510RL" 0603#1 3585.07,1300 r0 top
R7 "RC0603FR-07510RL" 0603#1 3585.07,1390 r0 top
R8 "RC0603JR-070RL" 0603#1 3125.07,1050 r90 top
R9 "RC0603FR-07510RL" 0603#1 3585.07,1210 r180 bottom
R10 "RC0603FR-07510RL" 0603#1 3585.07,1300 r180 bottom
R11 "RC0603FR-07510RL" 0603#1 3585.07,1390 r180 bottom
R12 "CRCW060310K0FKEA" 0603#1 3090,760 r270 top
R13 "CRCW060310K0FKEA" 0603#1 3300,760 r270 top
R14 "RC0603JR-070RL" 0603#1 3090.07,895 r90 top
R15 "RC0603JR-070RL" 0603#1 3440.07,895 r90 top
R16 "RC0603JR-070RL" 0603#1 3370.07,895 r90 top
R17 "RC0603JR-070RL" 0603#1 3230.07,895 r90 top
R18 "RC0603JR-070RL" 0603#1 3300.07,895 r90 top
R19 "RC0603JR-070RL" 0603#1 3160.07,895 r90 top
R20 "CRCW08050000Z0EA" 0805_HV 3860,2088.07 r90 top
R21 "ERJ-3GEY0R00V" 0603#1 3585.07,1070 r0 top
R22 "CRCW08050000Z0EA" 0805_HV 3750,2088.07 r90 top
R23 "CRCW08050000Z0EA" 0805_HV 370,2245 r270 top
R24 "RC0603JR-070RL" 0603#1 1255,1055 r270 top (schematic designator R1)
R25 "RC0603JR-070RL" 0603#1 1185.07,1055 r90 top (schematic designator R2)
R26 "RC0603JR-070RL" 0603#1 1115,1055 r270 top (schematic designator R3)
R27 "RC0603JR-070RL" 0603#1 1325,1055 r270 top (schematic designator R4)
R28 "RC0603FR-07510RL" 0603#1 2580.07,1210 r0 top (schematic designator R5)
R29 "RC0603FR-07510RL" 0603#1 2580.07,1300 r0 top (schematic designator R6)
R30 "RC0603FR-07510RL" 0603#1 2580.07,1390 r0 top (schematic designator R7)
R31 "RC0603JR-070RL" 0603#1 2120.07,1050 r90 top (schematic designator R8)
R32 "RC0603FR-07510RL" 0603#1 2580.07,1210 r180 bottom (schematic designator R9)
R33 "RC0603FR-07510RL" 0603#1 2580.07,1300 r180 bottom (schematic designator R10)
R34 "RC0603FR-07510RL" 0603#1 2580.07,1390 r180 bottom (schematic designator R11)
R35 "CRCW060310K0FKEA" 0603#1 2085,760 r270 top (schematic designator R12)
R36 "CRCW060310K0FKEA" 0603#1 2365,760 r270 top (schematic designator R166)
R37 "RC0603JR-070RL" 0603#1 2085.07,895 r90 top (schematic designator R14)
R38 "RC0603JR-070RL" 0603#1 2505.07,895 r90 top
R39 "RC0603JR-070RL" 0603#1 2435.07,895 r90 top (schematic designator R15)
R40 "RC0603JR-070RL" 0603#1 2295.07,895 r90 top (schematic designator R18)
R41 "RC0603JR-070RL" 0603#1 2365.07,895 r90 top (schematic designator R16)
R42 "RC0603JR-070RL" 0603#1 2225.07,895 r90 top (schematic designator R17)
R43 "RC0603JR-070RL" 0603#1 2155.07,895 r90 top (schematic designator R19)
R44 "ERJ-3GEY0R00V" 0603#1 2580.07,1070 r0 top (schematic designator R21)
R45 "CRCW060310K0FKEA" 0603#1 3725,230 r270 top
R46 "CRCW060310K0FKEA" 0603#1 3625,230 r270 top
R47 "CRCW06030000Z0EA" 0603#1 2990,690 r180 top
R48 "CRCW06030000Z0EA" 0603#1 2540,635 r0 top
R49 "CRCW06030000Z0EA" 0603#1 2735,535 r270 top
R50 "CRCW0603160KFKEA" 0603#1 3050,2605 r0 top
R51 "ERJ-8ENF3323V" 1206 3105.96,3540 r270 top
R52 "ERJ-8ENF3323V" 1206 3110,3330 r270 top
R53 "ERJ-8ENF3323V" 1206 3110,3115 r270 top
R54 "RC0603FR-0712RL" 0603#1 3010,2800 r270 top
R55 "CRCW0603649RFKEA" 0603#1 2980.96,3061.07 r0 top
R56 "CRCW0603649RFKEA" 0603#1 2980.96,2996.07 r0 top
R57 "CRCW0603100RFKEA" 0603#1 3035,1950 r270 top
R58 "CRCW0603100RFKEA" 0603#1 2965,1950 r270 top
R59 "CRCW08050000Z0EA" 0805_HV 2835,3050 r0 top
R60 "RC0603FR-0712RL" 0603#1 2945,2800 r270 top
R61 "ERJ-8ENF3323V" 1206 1885,3540 r270 top
R62 "ERJ-8ENF3323V" 1206 1885,3330 r270 top
R63 "ERJ-8ENF3323V" 1206 1885,3115 r270 top
R64 "RC0603FR-0712RL" 0603#1 1780,2810 r270 top
R65 "CRCW0603160KFKEA" 0603#1 1820,2610 r0 top
R66 "CRCW0603100RFKEA" 0603#1 1800,1950 r270 top
R67 "CRCW0603649RFKEA" 0603#1 1760,3061.02 r0 top
R68 "CRCW0603649RFKEA" 0603#1 1760,2996.02 r0 top
R69 "CRCW0603100RFKEA" 0603#1 1730,1950 r270 top
R70 "CRCW08050000Z0EA" 0805_HV 1610,3050 r0 top
R71 "RC0603FR-0712RL" 0603#1 1715,2810 r270 top
R72 "CRCW06030000Z0EA" 0603#1 2363.5,3475 r180 top
R73 "" 0603#1 2328.5,3665 r180 top
R74 "RC1206FR-07330KL" 1206 3990,3635 r180 top
R75 "CRCW060310K0FKEA" 0603#1 3871.73,2520 r270 bottom
R76 "RC1206FR-07330KL" 1206 185.37,3259.39 r180 top
R77 "CRCW060310K0FKEA" 0603#1 530,2660 r270 bottom
R78 "RC1206FR-07330KL" 1206 4050,3470 r90 top
R79 "RC0603FR-078K2L" 0603#2 3610,2910 r0 top
R80 "RC1206FR-07330KL" 1206 395.37,3259.39 r180 top
R81 "CRCW0603100RFKEA" 0603#1 3782.3,2519.78 r270 top
R82 "RC0603FR-078K2L" 0603#1 615,2805 r90 top
R83 "CRCW0603100RFKEA" 0603#1 440,2660 r270 top
R84 "RC1206FR-07330KL" 1206 4050,3265 r90 top
R85 "RC0603FR-078K2L" 0603#1 4030,2665 r90 top
R86 "RC0603FR-078K2L" 0603#1 685,2805 r90 top
R87 "RC1206FR-07330KL" 1206 605.37,3259.39 r180 top
R88 "RC0603FR-073K3L" 0603#1 3691.18,3206.07 r0 top
R89 "RC0603FR-073K3L" 0603#1 3691.18,3136.07 r0 top
R90 "RC0603FR-073K3L" 0603#1 660.37,3144.39 r0 top
R91 "RC0603FR-073K3L" 0603#1 660.37,3074.39 r0 top
R92 "CRCW060310K0FKEA" 0603#1 930,2410 r90 bottom
R93 "CRCW060310K0FKEA" 0603#1 4277.3,2275 r90 bottom
R94 "RC0603FR-078K2L" 0603#1 4175,2123.07 r270 top
R95 "RC0603FR-078K2L" 0603#1 835,2255 r270 top
R96 "CRCW0603100RFKEA" 0603#1 4366.41,2274.78 r90 top
R97 "CRCW0603100RFKEA" 0603#1 1020,2410 r90 top
R98 "RC0603FR-078K2L" 0603#1 4105,2123.07 r270 top
R99 "RC0603FR-078K2L" 0603#1 765,2255 r270 top
R100 "RC0603FR-0739RL" 0603#1 4205,1595 r90 top
R101 "RC0603FR-0739RL" 0603#1 4135,1595 r90 top
R102 "RC0603FR-0739RL" 0603#1 355.14,1945.98 r270 top
R103 "RC0603FR-0739RL" 0603#1 425.14,1945.98 r270 top
R104 "CRCW060310K0FKEA" 0603#1 4277.3,2520 r270 bottom
R105 "CRCW060310K0FKEA" 0603#1 930,2660 r270 bottom
R106 "RC0603FR-0739RL" 0603#1 955,3408.19 r180 top
R107 "RC0603FR-0739RL" 0603#1 955,3338.19 r180 top
R108 "RC0603FR-0739RL" 0603#1 4205,2926 r90 top
R109 "RC0603FR-0739RL" 0603#1 4140,2926 r90 top
R110 "RC0603FR-078K2L" 0603#1 4180,2665 r90 top
R111 "CRCW0603100RFKEA" 0603#1 4367.87,2520 r270 top
R112 "RC0603FR-078K2L" 0603#1 845,2805 r90 top
R113 "CRCW0603100RFKEA" 0603#1 1021.32,2660 r270 top
R114 "RC0603FR-078K2L" 0603#1 4110,2665 r90 top
R115 "RC0603FR-078K2L" 0603#1 775,2805 r90 top
R116 "CRCW060310R0JNEA" 0603#1 4000,2158.07 r180 top
R117 "CRCW060310R0JNEA" 0603#1 660,2290 r180 top
R118 "RC0603JR-070RL" 0603#1 4000,1993.07 r180 top
R119 "CRCW06031M00FKEA" 0603#1 3715,1975 r180 top
R120 "CRCW06031M00FKEA" 0603#1 1080,2110 r0 top
R121 "RC0603JR-070RL" 0603#1 660,2125 r180 top
R122 "CRCW060310K0FKEA" 0603#1 3465,1820 r90 top
R123 "CRCW060310K0FKEA" 0603#1 839.13,1943.05 r90 top
R124 "CRCW060310K0FKEA" 0603#1 3790,1715 r270 top
R125 "CRCW060310K0FKEA" 0603#1 1184.13,1865.05 r270 top
R126 "CRCW0603100RFKEA" 0603#1 4000,2088.07 r0 top
R127 "CRCW060310K0FKEA" 0603#1 3570,1900 r0 top
R128 "CRCW060310K0FKEA" 0603#1 964.13,2032.05 r0 top
R129 "CRCW0603100RFKEA" 0603#1 660,2220 r0 top
R130 "CRCW060314K0FKEA" 0603#1 4030,2665 r270 bottom
R131 "CRCW060314K0FKEA" 0603#1 685,2805 r270 bottom
R132 "RC1206FR-079K1L" 1206 3695,1680 r90 top
R133 "RC1206FR-079K1L" 1206 1074.13,1807.05 r90 top
R134 "CRCW06030000Z0EA" 0603#1 955,285 r0 top
R135 "" 0603#1 910,100 r0 top
R136 "CRCW0603100RFKEA" 0603#1 3390.07,1655 r270 top
R137 "CRCW0603100RFKEA" 0603#1 3300.07,1655 r270 top
R138 "CRCW0603100RFKEA" 0603#1 3215.07,1655 r270 top
R139 "CRCW08050000Z0EA" 0805_HV 490,2245 r90 top
R140 "CRCW060310K0FKEA" 0603#1 1735,165 r90 top
R141 "RC0603JR-070RL" 0603#1 4170,1700 r0 top
R142 "RC0603JR-070RL" 0603#1 390,1820 r180 top
R143 "CRCW0603100RFKEA" 0603#1 3810.13,1405 r90 top
R144 "CRCW0603100RFKEA" 0603#1 3740.13,1405 r90 top
R145 "CRCW0603100RFKEA" 0603#1 3950.13,1405 r90 top
R146 "CRCW0603100RFKEA" 0603#1 3880.13,1405 r90 top
R147 "CRCW0603100RFKEA" 0603#1 1185.07,1405 r90 top (schematic designator R143)
R148 "CRCW0603100RFKEA" 0603#1 1115.07,1405 r90 top (schematic designator R144)
R149 "CRCW0603100RFKEA" 0603#1 1325.07,1405 r90 top (schematic designator R145)
R150 "CRCW0603100RFKEA" 0603#1 1255.07,1405 r90 top (schematic designator R146)
R151 "CRCW08050000Z0EA" 0805_HV 3860,2268.07 r90 top
R152 "CRCW06032K55FKEA" 0603#1 3737.3,2264.78 r90 bottom
R153 "CRCW08050000Z0EA" 0805_HV 3738.62,2268.07 r90 top
R154 "CRCW08050000Z0EA" 0805_HV 490,2420 r90 top
R155 "CRCW06032K55FKEA" 0603#1 371.46,2420 r90 bottom
R156 "CRCW08050000Z0EA" 0805_HV 371.46,2420 r90 top
R157 "ERJ-3GEY0R00V" 0603#1 2813.57,1125 r0 top
R158 "CRCW0603100RFKEA" 0603#1 2295.07,1655 r270 top (schematic designator R136)
R159 "CRCW0603100RFKEA" 0603#1 2210.07,1655 r270 top (schematic designator R137)
R160 "CRCW0603100RFKEA" 0603#1 2125.07,1655 r270 top (schematic designator R138)
R161 "ERJ-3GEY0R00V" 0603#1 1785.07,1125 r0 top (schematic designator R157)
R162 "CRCW060310K0FKEA" 0603#1 2090,345 r90 top
R163 "CRCW060310K0FKEA" 0603#1 1975,345 r90 top
R164 "CRCW060310K0FKEA" 0603#1 3440,760 r270 top
R165 "CRCW060310K0FKEA" 0603#1 3230,760 r270 top
R166 "CRCW060310K0FKEA" 0603#1 3370,760 r270 top
R167 "CRCW060310K0FKEA" 0603#1 3160,760 r270 top
R168 "CRCW060310K0FKEA" 0603#1 4105,2123.07 r90 bottom
R169 "CRCW060310K0FKEA" 0603#1 765,2255 r90 bottom
R170 "RC0603JR-070RL" 0603#1 4175,3055 r0 top
R171 "RC0603JR-070RL" 0603#1 830,3375 r90 top
R172 "CRCW060310K0FKEA" 0603#1 4110,2665 r270 bottom
R173 "CRCW060310K0FKEA" 0603#1 775,2805 r270 bottom
R174 "CRCW060310K0FKEA" 0603#1 4175,2123.07 r90 bottom
R175 "CRCW060310K0FKEA" 0603#1 835,2255 r90 bottom
R176 "CRCW060310K0FKEA" 0603#1 4180,2665 r270 bottom
R177 "CRCW060310K0FKEA" 0603#1 845,2805 r270 bottom
R178 "CRCW060314K0FKEA" 0603#1 3961,2667 r270 bottom
R179 "CRCW060314K0FKEA" 0603#1 615,2805 r270 bottom
R180 "CRCW0603649RFKEA" 0603#1 2840,2770 r0 top
R181 "CRCW0603649RFKEA" 0603#1 1610,2780 r0 top
R182 "CRCW06030000Z0EA" 0603#1 2620,2025 r0 top
R183 "CRCW08050000Z0EA" 0805_HV 2120,2058 r270 top
R184 "CRCW0603649RFKEA" 0603#1 2840,2835 r0 top
R185 "CRCW0603649RFKEA" 0603#1 1610,2845 r0 top
T1 "750313638" Wurth_750313638 2370,2300 r90 top
TP1 "Pogo Pad" PogoPad 2695,935 r0 top
TP2 "Pogo Pad" PogoPad 3055.07,1035 r90 top
TP3 "Suggest using a net name here" Keystone1573-2 1855,620 r90 top
TP4 "Suggest using a net name here" Keystone1573-2 4367,2712 r0 top
TP5 "Suggest using a net name here" Keystone1573-2 1675,625 r90 top
TP6 "Pogo Pad" PogoPad 1690,940 r0 top
TP7 "Pogo Pad" PogoPad 2050.07,1035 r90 top locked (schematic designator TP2)
TP8 "Suggest using a net name here" Keystone1573-2 1022.5,2850 r0 top
TP9 "Pogo Pad" PogoPad 2488.5,3405 r90 top
TP10 "Pogo Pad" PogoPad 2213.5,2880 r90 top
TP11 "TP-040_RND" TP_H045P075 3782.3,2609.78 r0 top
TP12 "TP-040_RND" TP_H045P075 530,2750 r0 top
TP13 "TP-040_RND" TP_H045P075 4140,1750 r270 top
TP14 "TP-040_RND" TP_H045P075 591.07,1844.04 r90 top
TP15 "TP-040_RND" TP_H045P075 4366.98,2185 r90 top
TP16 "TP-040_RND" TP_H045P075 1020,2325 r90 top
TP17 "TP-040_RND" TP_H045P075 869.02,3177.79 r90 top
TP18 "TP-040_RND" TP_H045P075 3980,3020 r270 top
TP19 "TP-040_RND" TP_H045P075 4367.87,2610 r0 top
TP20 "TP-040_RND" TP_H045P075 1021.32,2745 r90 top
TP21 "TP-040_RND" TP_H045P075 4090,1993.07 r0 top
TP22 "TP-040_RND" TP_H045P075 740,2125 r90 top
TP23 "Pogo Pad" PogoPad 1000,410 r0 top
TP24 "Pogo Pad" PogoPad 2505.07,1000 r90 top
U1 "ADC104S021CIMM/NOPB" MUB10A_N 3845.13,1230 r180 top
U2 "ADS131A04IPBS" PBS0032A_N 3270.07,1229.34 r270 top
U3 "ADC104S021CIMM/NOPB" MUB10A_N 1220.07,1230 r180 top (schematic designator U1)
U4 "ADS131A04IPBS" PBS0032A_N 2265.07,1229.34 r270 top (schematic designator U2)
U5 "CDCLVC1102PW" PW0008A_N 2765,675 r180 top
U6 "AMC1200BDWV" DWV0008A 3000,2305 r270 top
U7 "AMC1200BDWV" DWV0008A 1765,2305 r270 top
U8 "TLV70450DBVR" DBV0005A_N 2363.5,3175 r180 top
U9 "SN6501DBVR" DBV0005A_N 2370,1890 r270 top
U10 "OPA4180ID" D0014A_N 4075.47,2396.56 r180 top
U11 "OPA4180ID" D0014A_N 731.17,2533.03 r180 top
U12 "LMV331IDBV" DBV0005A_N 3735,1860 r0 top
U13 "LM4040AIM3-2.5/NOPB" MF03A_N 3575,2188.07 r270 top
U14 "TLV70450DBVR" DBV0005A_N 820,660 r90 top
U15 "TPS71733DCKR" DCK0005A_N 405,1150 r90 top
U16 "TPS71725DCKR" DCK0005A_N 125,1150 r90 top
U17 "TPS60403DBVR" DBV0005A_N 820,930 r270 top
U18 "TPS72325DBVT" DBV0005A_N 1010,660 r270 top
U19 "LM4040AIM3-2.5/NOPB" MF03A_N 215,2335 r270 top
U20 "SN74LV1T34DBVR" DBV0005A_N 1700,350 r270 top
U21 "LMV331IDBV" DBV0005A_N 1129.13,1997.05 r0 top
Y1 "SG-210STF 16.3480ML" Epson_SG-210 2845,535 r90 top
ZZ1 "This Assembly Note is for PCB labels only" AssemblyNoteLabel 189,4398 r0 top
ZZ2 "These assemblies are ESD sensitive, ESD precautions shall be observed." AssemblyNote 189,4303 r0 top
ZZ3 "These assemblies must be clean and free from flux and all contaminants. Use of no clean flux is not acceptable." AssemblyNote 189,4203 r0 top
ZZ4 "These assemblies must comply with workmanship standards IPC-A-610 Class 2, unless otherwise specified." AssemblyNote 189,4108 r0 top

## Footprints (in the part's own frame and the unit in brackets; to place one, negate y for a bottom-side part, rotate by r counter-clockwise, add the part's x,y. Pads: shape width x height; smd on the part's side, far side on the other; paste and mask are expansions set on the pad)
0402 [mm] "0402 from SM-752 data"
  rect 0.8x0.6 smd: 1(-0.6,0) 2(0.6,0)
  silkscreen extent -1.22,-0.52 1.22,0.52, body extent -0.55,-0.3 0.55,0.3, height 0.6
0603#1 [mm] "0603 from SM-752 data"
  rect 1x0.95 smd: 1(-0.8,0) 2(0.8,0)
  silkscreen extent -1.52,-0.69 1.52,0.69, body extent -0.87,-0.47 0.87,0.47, height 1
0603#2 [mm] "0603 from SM-752 data"
  rect 0.95x1 smd: 1(8.915,-6.972) 2(8.915,-5.372)
  silkscreen extent 8.22,-7.7 9.61,-4.65, body extent 8.44,-7.05 9.39,-5.3, height 1
0805_HV [mil] "0805 with 30mil clearance between pads"
  rect 50x63 smd: 1(-40,0) 2(40,0)
  silkscreen extent -74,-40 74,40, body extent -43,-29 43,29, height 57
1206 [mm] "1206 from SM-752 data"
  rect 1.3x1.85 smd: 1(-1.45,0) 2(1.45,0)
  silkscreen extent -2.4,-1.21 2.4,1.21, body extent -1.7,-0.9 1.7,0.9, height 1.35
1210 [mm] "1210 from SM-752 data"
  rect 1.3x2.7 smd: 1(-1.45,0) 2(1.45,0)
  silkscreen extent -2.32,-1.57 2.32,1.57, body extent -1.7,-1.35 1.7,1.35, height 1.35
AssemblyNote [mil] "Assembly Note"
AssemblyNoteLabel [mil] "Assembly Note for PCB Labels"
CN2_MTB_P100_PD80_D1.1_S5.54X6.5_STACK [mil]
  rect 80x80 / inner round 80 / far side rect 80x80 hole 44: 1(-50,0)
  round 80 hole 44: 2(50,0)
  silkscreen extent -100,-128 100,160
CONN_ED120-2DS [mm] "ONSHORE"
  rect 1.75x1.75 hole 1.25: 1(0,-2.54)
  round 1.75 hole 1.25: 2(0,2.54)
  silkscreen extent -5,-5.6 4,5.12, body extent -5,-5.6 4.15,5.12, height 13.1
D0014A_N [mm] "SOIC, 14-Leads, Body 8.7x3.9mm, Pitch 1.27mm, IPC Medium Density"
  oval 1.45x0.6 smd: 1(-2.725,3.81) 2(-2.725,2.54) 3(-2.725,1.27) 4(-2.725,0) 5(-2.725,-1.27) 6(-2.725,-2.54) 7(-2.725,-3.81) 8(2.725,-3.81) 9(2.725,-2.54) 10(2.725,-1.27) 11(2.725,0) 12(2.725,1.27) 13(2.725,2.54) 14(2.725,3.81)
  silkscreen extent -3.3,-4.4 0.9,4.4, body extent -3.02,-4.32 3.02,4.32, height 1.6
DBV0005A_N [mm] "SOT23, 5-Leads, Body 2.9x1.6mm, Pitch 0.95mm, Lead Span 2.8mm, IPC Medium Density"
  rrect17% 1x0.6 smd: 1(-1.375,0.95) 2(-1.375,0) 3(-1.375,-0.95) 4(1.375,-0.95) 5(1.375,0.95)
  silkscreen extent -1.63,-1.55 0.38,1.55, body extent -1.42,-1.46 1.42,1.46, height 1.09
DCK0005A_N [mm] "SOT353, 5-Leads, Body 2x1.3mm, Pitch 0.65mm, Lead Span 2.1mm, IPC Medium Density"
  rrect25% 0.85x0.4 smd: 1(-1.125,0.65) 2(-1.125,0) 3(-1.125,-0.65) 4(1.125,-0.65) 5(1.125,0.65)
  silkscreen extent -1.48,-1.02 0.55,1.1, body extent -1.14,-1 1.14,1, height 0.95
DIO_SOD323 [mm] "TVS DIODE, SOD323, SMT"
  rect 1.2x0.35 smd: 1(-1.25,0) 2(1.25,0)
  Top Layer region: -0.356,0.25 -0.357,-0.227 0.417,-0.227 0.415,0.25
  silkscreen extent -5.03,-0.65 1.25,0.65, body extent -1.25,-0.63 1.25,0.63, height 1.1
DWV0008A [mm] "SOIC, 8-Leads, Body 5.95x7.6mm (max), Pitch 1.27mm"
  rrect17% 1.8x0.6 smd: 1(-5.45,1.905) 2(-5.45,0.635) 3(-5.45,-0.635) 4(-5.45,-1.905) 5(5.45,-1.905) 6(5.45,-0.635) 7(5.45,0.635) 8(5.45,1.905)
  silkscreen extent -6.25,-2.95 2.98,2.95, body extent -5.77,-2.92 5.77,2.93, height 2.67
Epson_SG-210 [mm] "SMD, 2-Leads, Body 2x2.5mm"
  rect 0.9x1.1 smd: 1(-0.65,0.85) 2(-0.65,-0.85) 3(0.65,-0.85) 4(0.65,0.85)
  silkscreen extent -1.4,-1.7 1.4,1.7, body extent -1.08,-1.33 1.08,1.33, height 0.91
ESD_Overlay_small [mil]
  silkscreen extent -62,-48 64,61
Fiducial10-20 [mm]
  round 1 smd mask+0.5: 1(0,0)
  Top Layer keep-out circle w1.178: c0,0 r0.5
IEC_HighVoltage_medium [mil]
  silkscreen extent -217,-176 217,200
Keystone1573-2 [mm] "Double Turret"
  round 2.7 hole 2.05: 1(0,0)
  silkscreen extent -1.73,-1.73 1.73,1.73, body extent -1.18,-1.18 1.17,1.18, height 4.72
Keystone_1902C [mil] "Hex Standoff, 4-40 threaded, nylon"
  round 1 on Mech4: 0(0,0)
  body extent -145,-126 146,126, height 501
Label_650x200 [mil] "Thermal Transfer Label"
  round 1 on Mech13: 0(0,0)
  silkscreen extent -325,-100 325,100, body extent -325,-100 325,100, height 1
LED0603AA [mil]
  rect 32x32 smd: 1(-32.48,0) 2(32.48,0)
  silkscreen extent -16,-74 58,16
MF03A_N [mm] "SOT23, 3-Leads, Body 2.9x1.3mm, Pitch 0.95mm, Lead Span 2.4mm, IPC Medium Density"
  rect 1.3x0.6 smd: 1(-1.05,0.95) 2(-1.05,-0.95) 3(1.05,0)
  silkscreen extent -1.17,-1.5 0.7,1.93, body extent -0.7,-1.5 0.7,1.5, height 1.12
MMZ1608_095 [mm] "TDK"
  rect 0.6x0.8 smd: 1(-0.7,0) 2(0.7,0)
  silkscreen extent -0.15,-0.58 0.15,0.58, body extent -0.87,-0.47 0.87,0.47, height 0.95
MUB10A_N [mm] "TSSOP, 10-Leads, Body 3x3mm, Pitch 0.5mm, IPC Medium Density"
  oval 1.7x0.3 smd: 1(-2.05,1) 2(-2.05,0.5) 3(-2.05,0) 4(-2.05,-0.5) 5(-2.05,-1) 6(2.05,-1) 7(2.05,-0.5) 8(2.05,0) 9(2.05,0.5) 10(2.05,1)
  silkscreen extent -2.17,-1.6 0.8,1.82, body extent -1.6,-1.6 1.6,1.6, height 1.09
"NY PMS 440 0025 PH" [mm] "4-40 nylon screw and mounting hole"
  round 8 hole 3.2: 1(0,0)
  body extent -3.3,-3.3 3.3,3.3, height 2.69
Pb-Free_Overlay_Small [mil]
  silkscreen extent -46,-46 46,46
PBS0032A_N [mm]
  oval 1.4x0.3 smd: 1(-3.2,1.75) 2(-3.2,1.25) 3(-3.2,0.75) 4(-3.2,0.25) 5(-3.2,-0.25) 6(-3.2,-0.75) 7(-3.2,-1.25) 8(-3.2,-1.75) 17(3.2,-1.75) 18(3.2,-1.25) 19(3.2,-0.75) 20(3.2,-0.25) 21(3.2,0.25) 22(3.2,0.75) 23(3.2,1.25) 24(3.2,1.75)
  oval 0.3x1.4 smd: 9(-1.75,-3.2) 10(-1.25,-3.2) 11(-0.75,-3.2) 12(-0.25,-3.2) 13(0.25,-3.2) 14(0.75,-3.2) 15(1.25,-3.2) 16(1.75,-3.2) 25(1.75,3.2) 26(1.25,3.2) 27(0.75,3.2) 28(0.25,3.2) 29(-0.25,3.2) 30(-0.75,3.2) 31(-1.25,3.2) 32(-1.75,3.2)
  silkscreen extent -3.6,-2.53 2.53,2.53, body extent -3.51,-3.51 3.51,3.51, height 1.2
PogoPad [mil] "No Solder Paste"
  round 70 smd paste-35: 1(0,0)
PW0008A_N [mm] "TSOP, 8-Leads, Body 3x4.4mm, Pitch 0.65mm, IPC Medium Density"
  oval 1.4x0.45 smd: 1(-2.95,0.975) 2(-2.95,0.325) 3(-2.95,-0.325) 4(-2.95,-0.975) 5(2.95,-0.975) 6(2.95,-0.325) 7(2.95,0.325) 8(2.95,0.975)
  silkscreen extent -3.4,-1.55 1.85,1.55, body extent -3.21,-1.5 3.21,1.5, height 1.2
SOD-123 [mm] "On Semi recommended land pattern"
  rect 0.915x1.22 smd: 1(-1.637,0) 2(1.637,0)
  silkscreen extent -2.74,-1.17 2.03,1.17, body extent -1.93,-0.9 1.93,0.9, height 1.35
SOT-23 [mm] "SOT23, 3-Leads, Body 2.9x1.3mm, Pitch 0.95mm, Lead Span 2.5mm, IPC Medium Density"
  rrect50% 1x0.6 smd: 1(-1.2,0.95) 2(-1.2,-0.95) 3(1.2,0)
  silkscreen extent -1.63,-1.5 0.7,1.5, body extent -1.16,-1.45 1.21,1.45, height 1
SOT-323 [mm] "Zetex recommended land pattern.  March 2007"
  rect 0.8x0.6 smd: 1(-0.8,0.65) 2(-0.8,-0.65) 3(0.8,0)
  silkscreen extent -1.14,-1.22 0.77,1.22, body extent -1.13,-1.13 1.12,1.12, height 1.13
TE_5-146280-3 [mm] "Header, 2.54mm, 3x1, TH"
  rect 0.76x2.29 hole 0.89: 1(-2.54,0) 2(0,0) 3(2.54,0)
  silkscreen extent -3.9,-1.17 3.61,1.17, body extent -3.61,-1.17 3.61,1.17, height 8.13
TP_H045P075 [mil] "TP_H0.45P0.75"
  round 35 hole 17.72: 1(0,0)
TSW-102-07-G-S [mm] "Samtec 100mil, 1x2, 230 mil above insulator"
  rrect6% 1.65x1.65 hole 1.016: 1(-1.27,0)
  round 1.65 hole 1.016: 2(1.27,0)
  silkscreen extent -2.54,-1.27 2.54,1.65, body extent -2.54,-1.27 2.54,1.27, height 8.38
Wurth_750313638 [mm] "SMD, 6-Leads, Body 8x9.14mm, Pitch 3.05mm"
  rect 1.9x1.14 smd: 1(-5.655,3.05) 2(-5.655,0) 3(-5.655,-3.05) 4(5.655,-3.05) 5(5.655,0) 6(5.655,3.05)
  silkscreen extent -4,-4.57 4,4.87, body extent -6.35,-4.57 6.35,4.57, height 7.62
WURTH_61301021121 [mm] "Header, 2.54mm, 5x2, TH"
  rect 1.65x1.65 hole 1.15: 1(-5.08,-1.27)
  round 1.65 hole 1.15: 2(-5.08,1.27) 3(-2.54,-1.27) 4(-2.54,1.27) 5(0,-1.27) 6(0,1.27) 7(2.54,-1.27) 8(2.54,1.27) 9(5.08,-1.27) 10(5.08,1.27)
  silkscreen extent -6.35,-2.54 6.35,2.9, body extent -6.35,-2.54 6.35,2.54, height 8.54

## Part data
C1 C16 C35 C36 C40 C41: library part 06033C104JAT2A, "CAP, CERM, 0.1uF, 25V, +/-5%, X7R, 0603"
C2 C17 C81: "CAP, CERM, 10uF, 35V, +/-10%, X7R, 1206"
C3 C8 C20 C27 C114: "CAP, CERM, 0.1 µF, 25 V, +/- 5%, X7R, 0603"
C4 C21: "CAP, CERM, 10 µF, 10 V, +/- 10%, X7R, 0805"
C5 C9 C11 C18 C22 C24 C95 C97 C99 C116 C117 C130 C131 C132 C133 C134 C135 C136 C137: "CAP, CERM, 0.01 µF, 100 V, +/- 10%, X7R, 0603"
C6 C7 C10 C12 C14 C15 C19 C23 C25 C26 C29 C30 C87 C88 C90 C91 C93 C94 C96 C98: "CAP, CERM, 1 µF, 25 V, +/- 10%, X7R, 0603"
C13 C28: "CAP, CERM, 0.27 µF, 16 V, +/- 10%, X7R, 0603"
C31: "CAP, CERM, 0.1uF, 16V, +/-10%, X7R, 0603"
C32 C82: "CAP, CERM, 0.01uF, 50V, +/-10%, C0G/NP0, 0402"
C33 C83: "CAP, CERM, 1000pF, 25V, +/-10%, X5R, 0402"
C34 C84: "CAP, CERM, 100pF, 50V, +/-10%, X7R, 0402"
C37 C38 C42 C43: "CAP, CERM, 1 µF, 16 V, +/- 10%, X7R, 0603"
C39 C44: "CAP, CERM, 330 pF, 50 V, +/- 10%, C0G/NP0, 0805"
C45 C49 C50 C52 C80 C85: library part GMK325AB7106MM-T, "CAP, CERM, 10uF, 35V, +/-20%, X7R, 1210"
C46 C48 C51 C53 C79 C86: library part C0603C104K5RACTU, "CAP, CERM, 0.1uF, 50V, +/-10%, X7R, 0603"
C47 C78: library part C2012X5R1H475K125AB, "4.7µF ±10% 50V X5R Ceramic Capacitor -55°C ~ 85°C"
C54 C55 C62 C63 C65 C66 C70 C71 C72 C73: "CAP, CERM, 100pF, 25V, +/-10%, X7R, 0603"
C56 C59 C64 C69 C76 C77 C101 C115: "CAP, CERM, 0.1uF, 25V, +/-5%, X7R, 0603"
C57 C58 C67 C68 C74 C75 C102 C103 C104 C107 C108 C109 C110 C111 C112 C113: "CAP, CERM, 100 pF, 25 V, +/- 10%, X7R, 0603"
C60 C61: "CAP, CERM, 1000pF, 50V, +/-5%, C0G/NP0, 0603"
C89 C92 C100 C105 C106: "CAP, CERM, 1000 pF, 100 V, +/- 5%, X7R, 0603"
C118 C120: "CAP, CERM, 1 µF, 25 V, +/- 10%, X5R, 0603"
C119 C121: "CAP, CERM, 0.1 µF, 50 V, +/- 10%, X7R, 0603"
C122 C123 C124 C125 C126 C127 C128 C129: "CAP, CERM, 47 pF, 50 V, +/- 5%, C0G/NP0, 0805"
D1 D2 D3 D4 D5 D6 D7 D8: library part BAV99WT1G, "Diode, P-N, 70V, 0.2A, SOT-323"
D9 D12: library part MBR0520LT1G, "Diode, Schottky, 20V, 0.5A, SOD-123"
D10 D15: "Diode, Zener, 5.6 V, 500 mW, SOD-123"
D11 D16: library part "LED_LG L29K-G2J1-24-Z", "LED SmartLED Green 570NM"
D13 D14: "Diode, Switching, 200V, 0.2A, SOT-23"
D17: "Diode, Zener, 3.6 V, 500 mW, SOD-123"
D18 D19: "Diode, Zener, 3 V, 500 mW, SOD-123"
D20: "Diode, Schottky, 20 V, 0.5 A, SOD-123"
D21 D22 D23 D24 D25 D26 D27 D28: "DIODE, TVS, BIDIRECTIONAL, 3.3VWM, 26VC, SOD323"
FID1 FID2 FID3 FID4 FID5 FID6: "Fiducial mark.  There is nothing to buy or mount."
H1 H2 H3 H4: "Machine Screw, Round, #4-40 x 1/4, Nylon, Philips panhead"
H5 H6 H7 H8: "Standoff, Hex, 0.5\"L #4-40 Nylon"
J1 J2: "Header, 2.54 mm, 5x2, Gold, TH"
J3 J4 J5 J6 J13: "TERMINAL BLOCK 5.08MM VERT 2POS, TH"
J7 J8 J9 J10 J15: "Terminal Block, 4x1, 2.54mm, TH"
J11 J12 J14: "Header, 2.54mm, 3x1, Gold, TH"
JP1 JP2 JP3 JP4 JP5 JP6 JP7 JP8 JP9: library part TSW-102-07-G-S, "Header, 100mil, 2x1, Gold, TH"
L1 L2 L3 L4 L5: "Ferrite Bead, 1000 ohm @ 100 MHz, 0.3 A, 0603"
LBL1: library part THT-14-423-10, "Thermal Transfer Printable Labels, 0.650\" W x 0.200\" H - 10,000 per roll"
Logo3: library part Pb-Free
LOGO4: library part IEC_HighVoltage, "IEC 61010-1 High Voltage Warning"
Pb_Free: library part ESD_Susceptible, "ESD Susceptible Symbol"
R1 R2 R3 R4 R8 R14 R15 R16 R17 R18 R19 R21 R24 R25 R26 R27 R31 R37 R38 R39 R40 R41 R42 R43 R44 R118 R121 R141 R142 R157 R161 R170 R171: "RES, 0, 5%, 0.1 W, 0603"
R5 R6 R7 R9 R10 R11 R28 R29 R30 R32 R33 R34: "RES, 510, 1%, 0.1 W, 0603"
R12 R13 R35 R36 R45 R46 R75 R77 R92 R93 R104 R105 R122 R123 R127 R128 R164 R165 R166 R167 R168 R169 R172 R173 R174 R175 R176 R177: library part RNCF0603TKY10K0, "RES, 10.0k ohm, 1%, 0.1W, 0603"
R20 R22 R23 R59 R70 R139 R151 R153 R154 R156 R183: "RES, 0 ohm, 5%, 0.125W, 0805"
R47 R48 R49 R72 R134 R182: "RES, 0 ohm, 5%, 0.1W, 0603"
R50 R65: "RES, 160 k, 1%, 0.1 W, 0603"
R51 R52 R53 R61 R62 R63: "RES, 332 k, 1%, 0.25 W, 1206"
R54 R60 R64 R71: "RES, 12.0, 1%, 0.1 W, 0603"
R55 R56 R67 R68 R180 R181 R184 R185: "RES, 649, 1%, 0.1 W, 0603"
R57 R58 R66 R69 R81 R83 R96 R97 R111 R113 R126 R129 R136 R137 R138 R143 R144 R145 R146 R147 R148 R149 R150 R158 R159 R160: "RES, 100 ohm, 1%, 0.1W, 0603"
R73 R135: library part CRCW06033K90JNEA, "RES, 3.9k ohm, 5%, 0.1W, 0603"
R74 R76 R78 R80 R84 R87: "RES, 330 k, 1%, 0.25 W, 1206"
R79 R82 R85 R86 R94 R95 R98 R99 R110 R112 R114 R115: "RES, 8.20 k, 1%, 0.1 W, 0603"
R88 R89 R90 R91: "RES, 3.30 k, 1%, 0.1 W, 0603"
R100 R101 R102 R103 R106 R107 R108 R109: "RES, 39.0, 1%, 0.1 W, 0603"
R116 R117: "RES, 10, 5%, 0.1 W, 0603"
R119 R120: "RES, 1.00Meg ohm, 1%, 0.1W, 0603"
R124 R125: "RES, 10.0k ohm, 1%, 0.1W, 0603"
R130 R131 R178 R179: "RES, 14.0 k, 1%, 0.1 W, 0603"
R132 R133: "RES, 9.10 k, 1%, 0.25 W, 1206"
R140 R162 R163: "RES, 10.0 k, 1%, 0.1 W, 0603"
R152 R155: "RES, 2.55 k, 1%, 0.1 W, 0603"
T1: library part 750313734, "Transformer, 340 uH, TH"
TP1 TP2 TP6 TP7 TP9 TP10 TP23 TP24: library part PogoPad, "Pad for Pogo Pin Connector"
TP3 TP4 TP5 TP8: library part 1573-2, "Terminal, Turret, TH, Double"
TP11 TP12 TP13 TP14 TP15 TP16 TP17 TP18 TP19 TP20 TP21 TP22: "Test Point, O.040 Hole"
U1 U3: "4 Channel, 50 kSPS to 200 kSPS, 10-Bit A/D Converter, 10-pin Mini SOIC, Pb-Free"
U2 U4: "Four Channel Analog Front-End for Power Monitoring, Control, and Protection, PBS0032A"
U5: "3.3 V and 2.5 V LVCMOS High-Performance Clock Buffer Family, PW0008A"
U6 U7: "Fully-Differential Isolation Amplifier, DWV0008A"
U8 U14: "Single Output LDO, 150 mA, Fixed 5 V Output, 2.5 to 24 V Input, with Ultra-Low IQ, 5-pin SOT-23 (DBV), -40 to 125 degC, Green (RoHS & no Sb/Br)"
U9: "Transformer Driver for Isolated Power Supplies, DBV0005A"
U10 U11: "0.1 uV/C Drift, Quad, Low Noise, Rail-to-Rail, Zero Drift Operational Amplifier, 4 to 36 V, -40 to 105 degC, 14-pin SOIC (D0014A), Green (RoHS & no Sb/Br)"
U12 U21: "Single General Purpose Low-Voltage Comparator, DBV0005A"
U13 U19: "Precision Micropower Shunt Voltage Reference, 3-pin SOT-23, Pb-Free"
U15: "Single Output High PSRR LDO, 150 mA, Fixed 3.3 V Output, 2.5 to 6.5 V Input, with Low IQ, 5-pin SC70 (DCK), -40 to 85 degC, Green (RoHS & no Sb/Br)"
U16: "Single Output High PSRR LDO, 150 mA, Fixed 2.5 V Output, 2.5 to 6.5 V Input, with Low IQ, 5-pin SC70 (DCK), -40 to 85 degC, Green (RoHS & no Sb/Br)"
U17: "-1.8 to -5.25 V, Inverting Charge Pump Regulator, 60 mA, 1.8 to 5.25 V Input with 2-Cell Alkaline / Nixx Input, -40 to 85 degC, 5-pin SOT23 (DBV5), Green (RoHS & no Sb/Br)"
U18: "Single Output High PSRR LDO, 200 mA, Fixed -2.5 V Output, -10 to -2.7 V Input, 5-pin SOT-23 (DBV), -40 to 125 degC, Green (RoHS & no Sb/Br)"
U20: "Single Power Supply Single Buffer GATE CMOS Logic Level Shifter, DBV0005A"
Y1: library part "SG-210STF 13.5600ML", "Oscillator, 13.56MHz, 1.6 to 3.6 V, SMD"
ZZ1: library part AssemblyNoteLabel
ZZ2 ZZ3 ZZ4: library part AssemblyNote

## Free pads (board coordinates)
  round 0 hole 120 slot 394 at 0 deg unplated mask+5: 2(1765,2315) 2(3000,2315)
  round 0 hole 120 slot 550 at 0 deg unplated mask+5: 2(2370,2315)

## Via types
v1: diameter 24, hole 12, Top Layer to Bottom Layer, tented both sides, 309 vias
v2: diameter 32, hole 16, Top Layer to Bottom Layer, tented both sides, 35 vias

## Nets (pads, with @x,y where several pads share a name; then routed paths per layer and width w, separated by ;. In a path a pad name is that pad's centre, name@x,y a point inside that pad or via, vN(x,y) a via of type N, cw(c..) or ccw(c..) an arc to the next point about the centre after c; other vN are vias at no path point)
3.3V: C88.1 D17.1 J11.1 L5.1 U15.5 | length 346.9
  Top Layer w20: D17.1@380.53,1375 380.53,1380.53 417.44,1417.44 L5.1@417.44,1485
  Bottom Layer w25: J11.1@310,1640 310,1475 v1(350,1435)
+2P5V: C91.1 D18.1 J11.3 U16.5 | length 265.2
  Top Layer w20: J11.3@110,1640 110,1375.53 D18.1@110.53,1375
